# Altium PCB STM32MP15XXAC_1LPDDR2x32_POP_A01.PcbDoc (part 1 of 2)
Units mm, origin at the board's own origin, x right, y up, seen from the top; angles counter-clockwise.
Board outline 89 x 120 mm, 6 copper layers (Top Layer, Signal Layer 1, Signal Layer 2, Signal Layer 3, Signal Layer 4, Bottom Layer), stack 1.556 mm thick; 87 components, 99 nets, 895 pads, 462 vias.
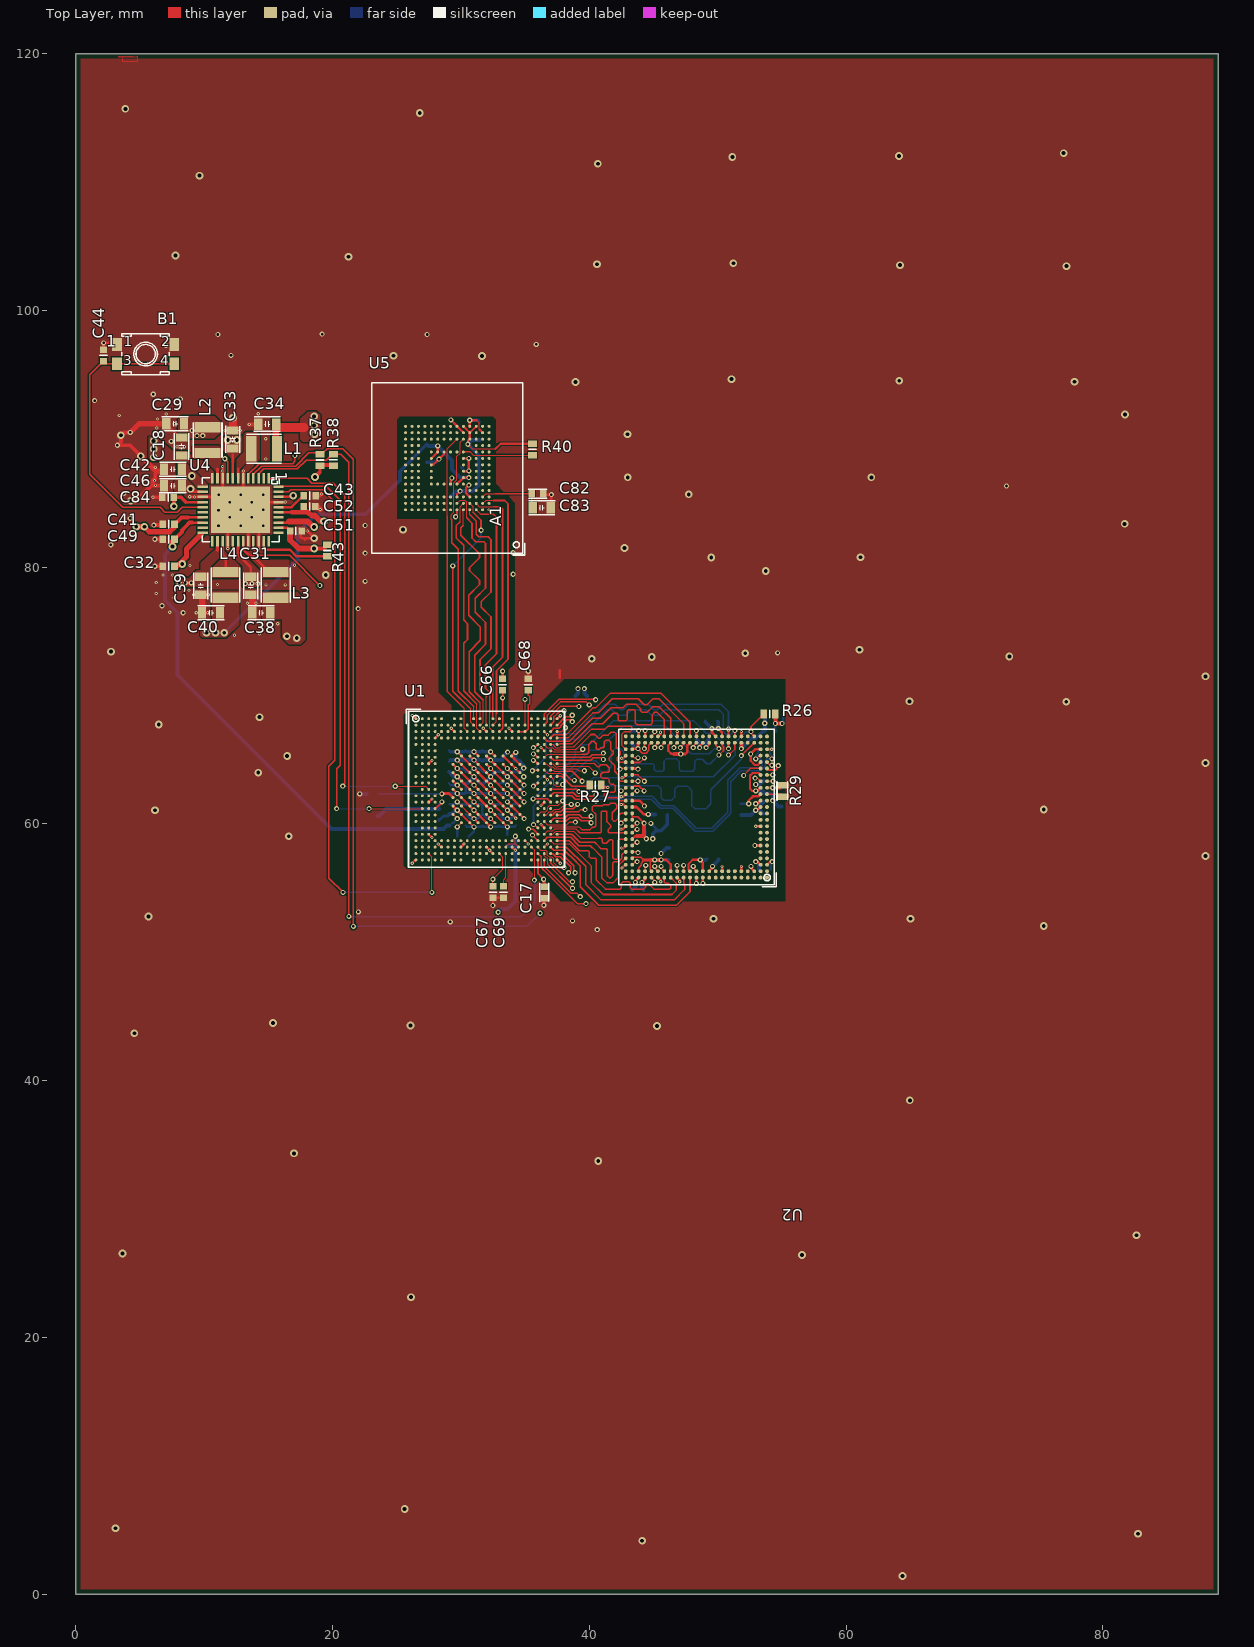
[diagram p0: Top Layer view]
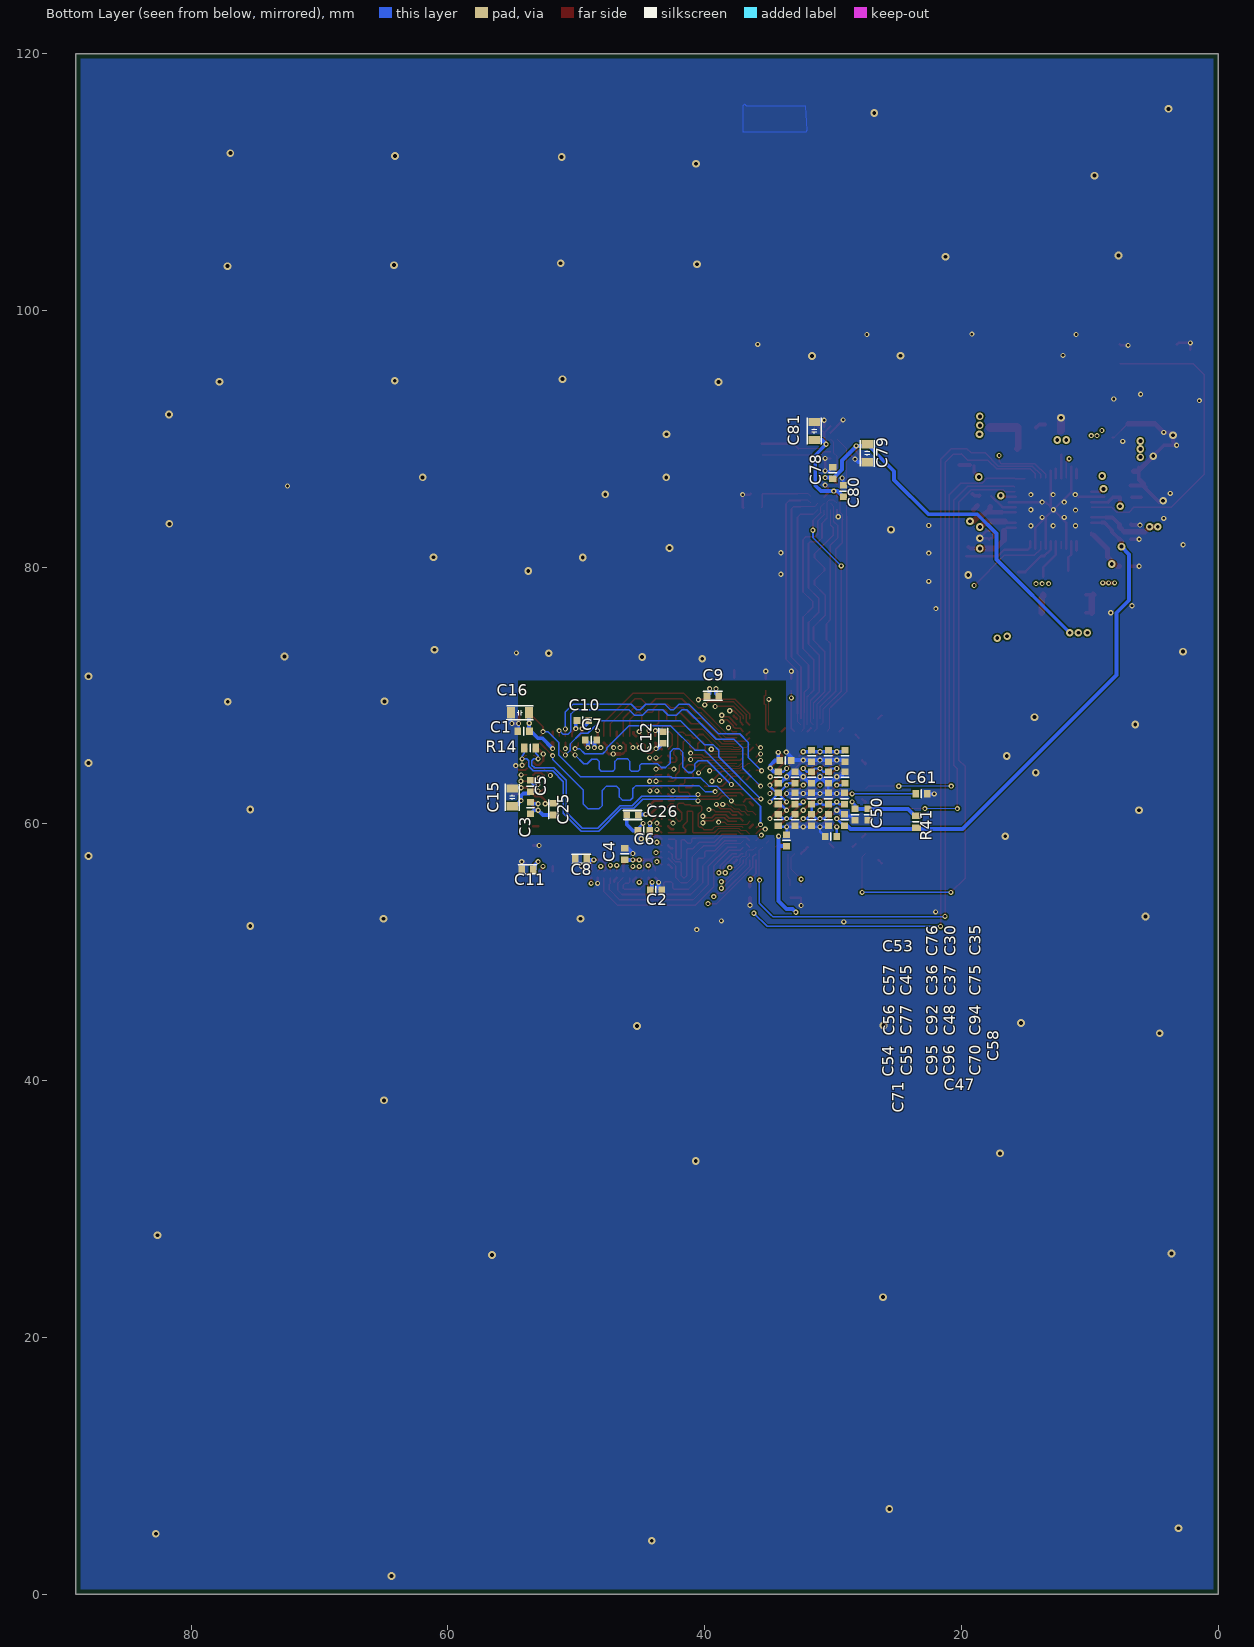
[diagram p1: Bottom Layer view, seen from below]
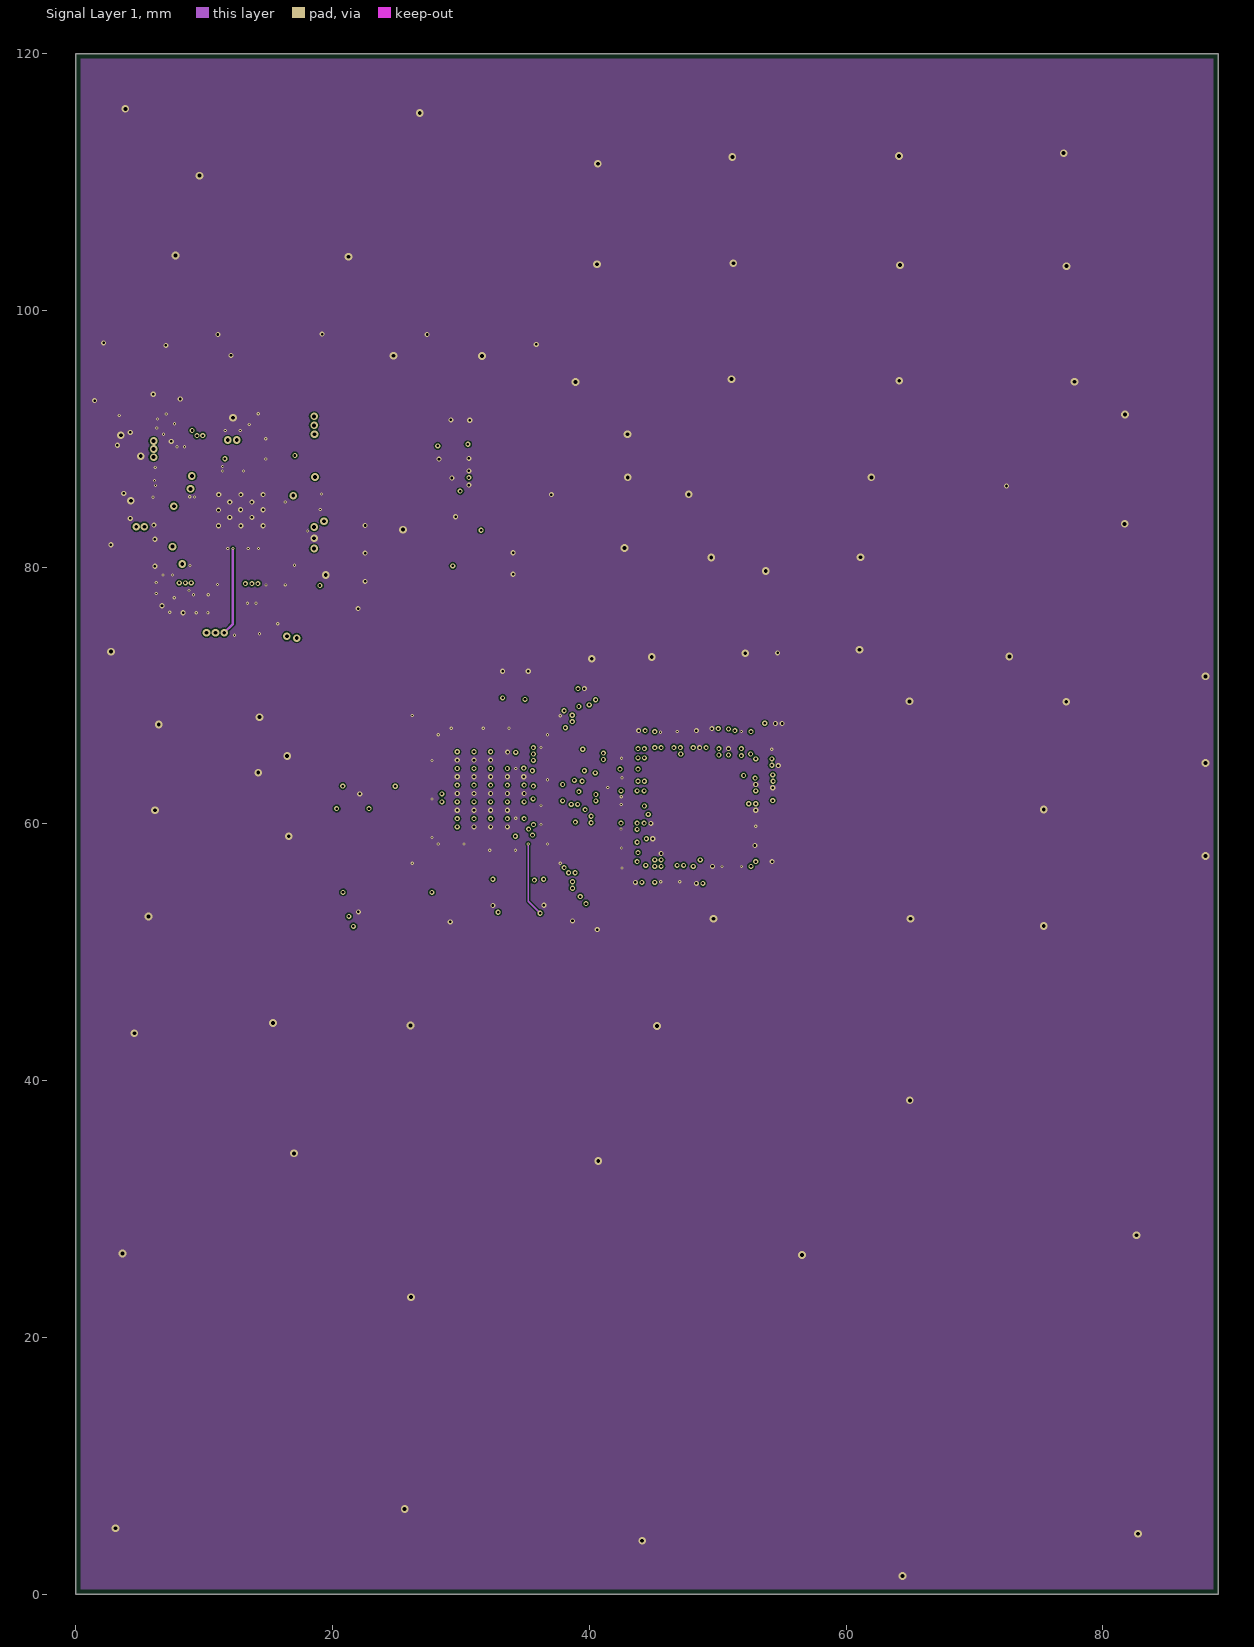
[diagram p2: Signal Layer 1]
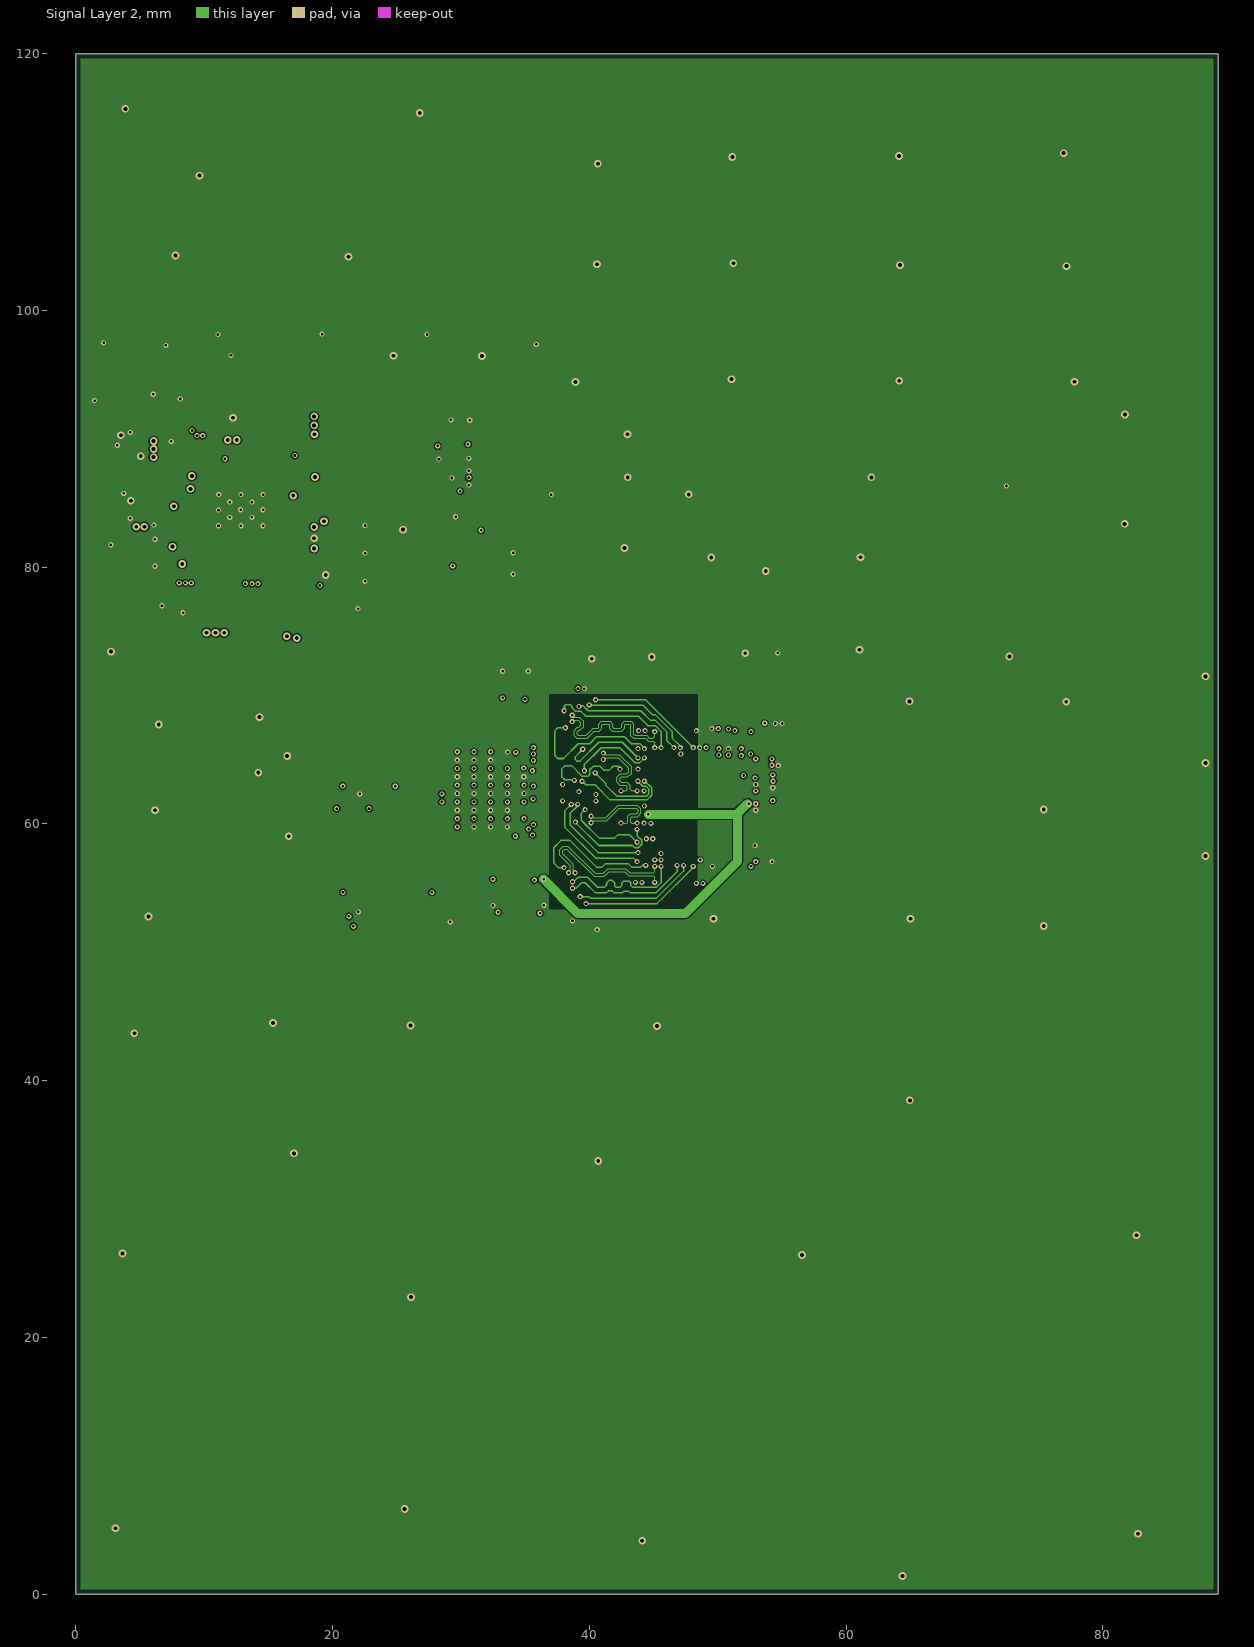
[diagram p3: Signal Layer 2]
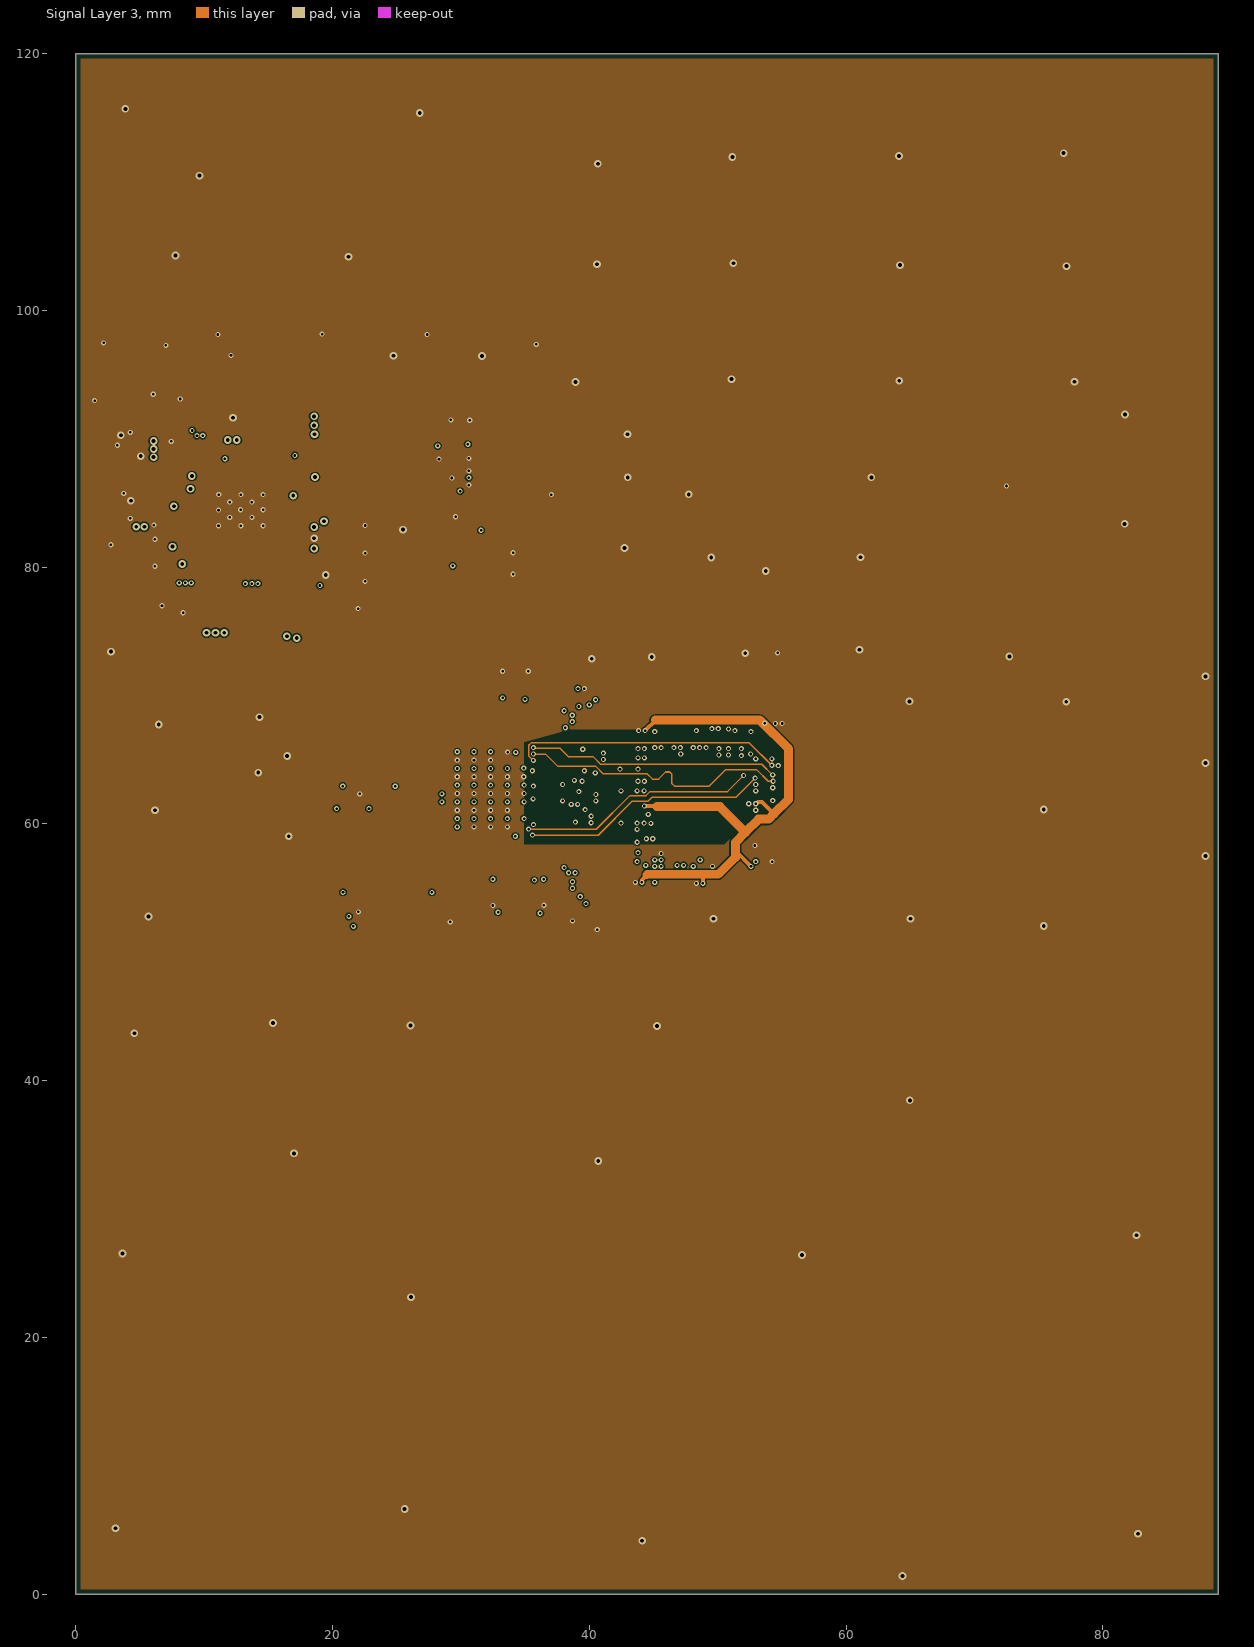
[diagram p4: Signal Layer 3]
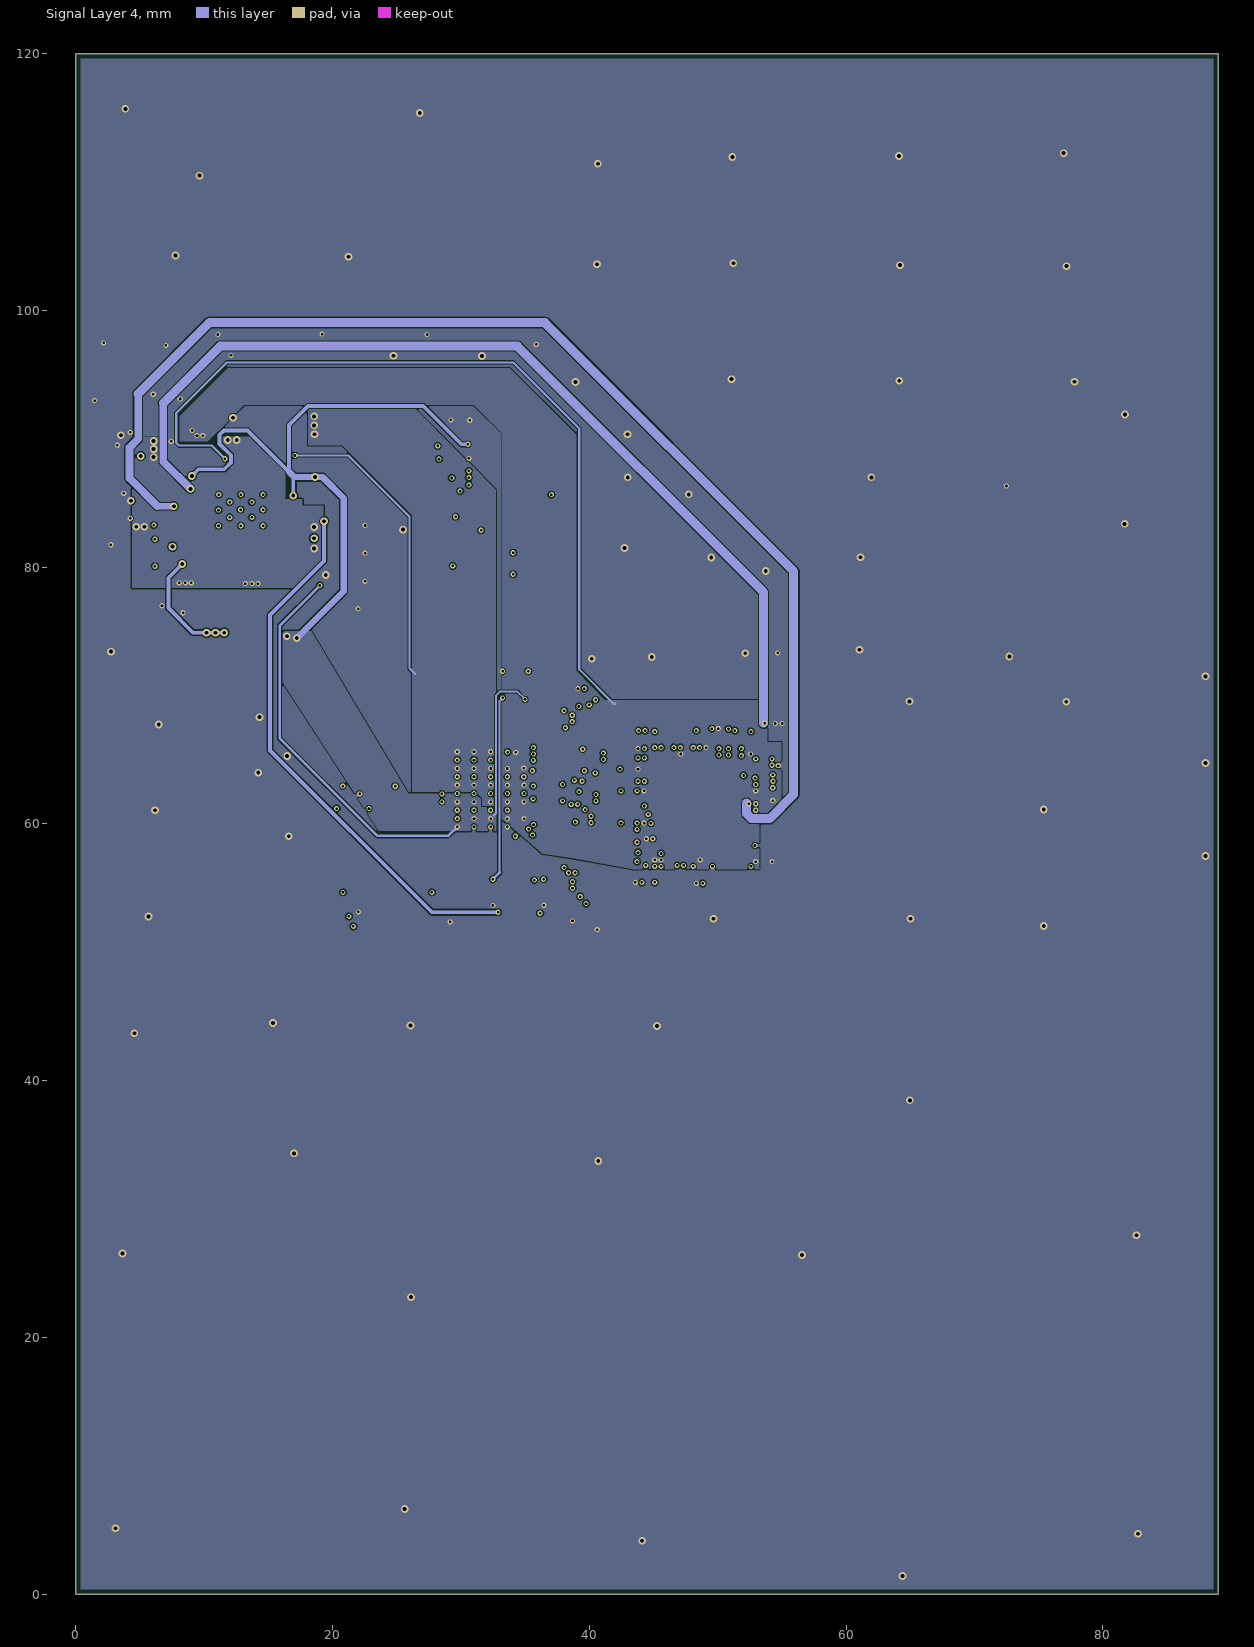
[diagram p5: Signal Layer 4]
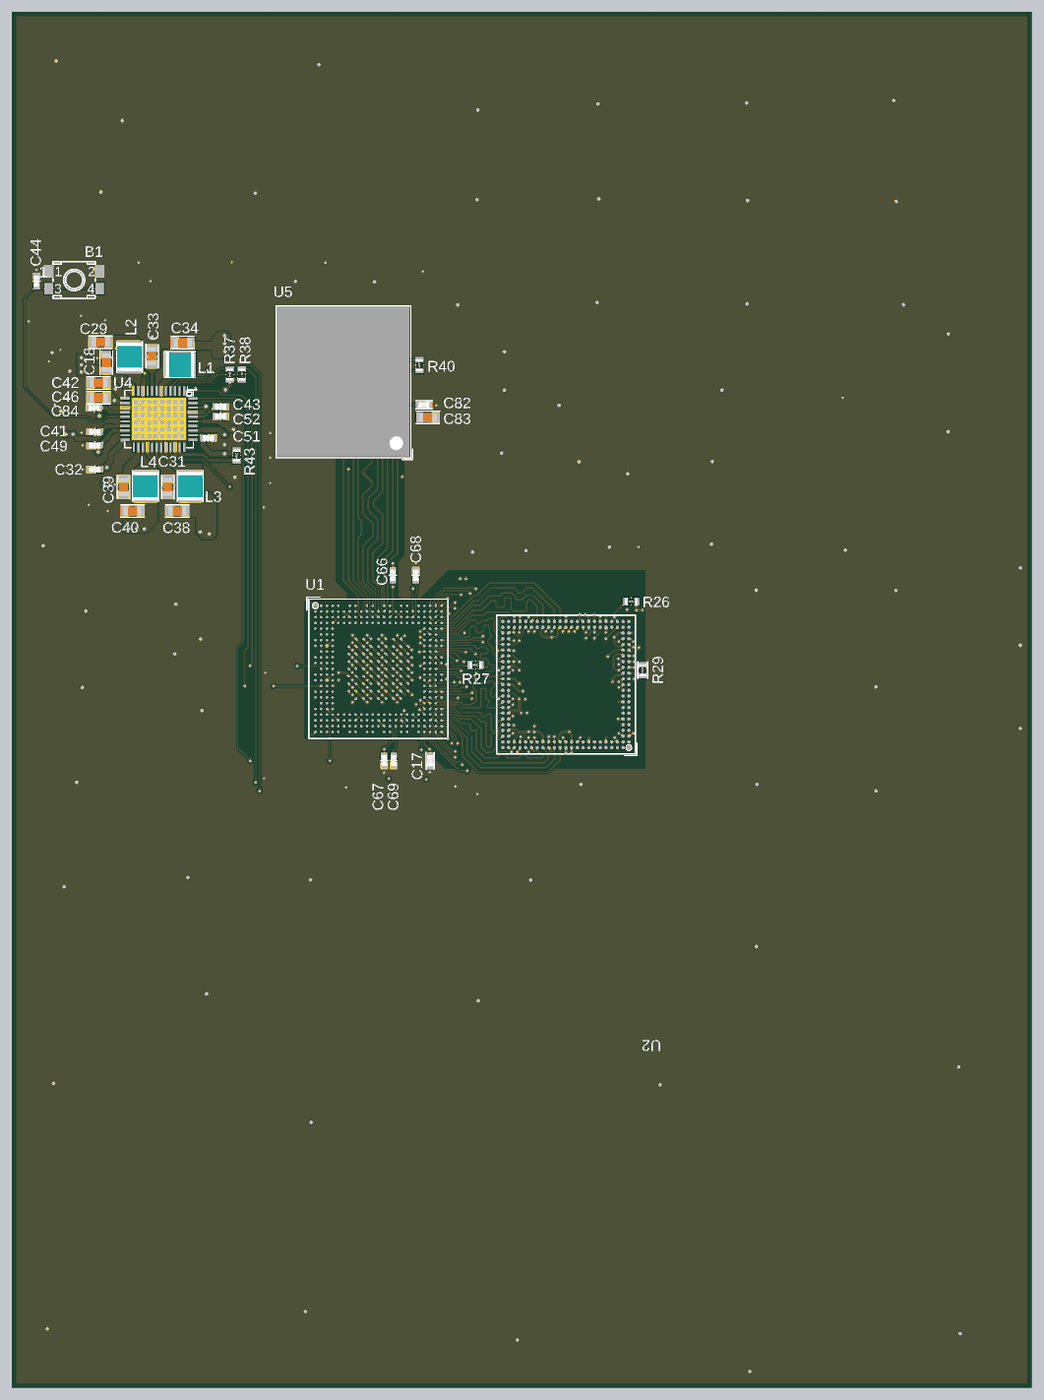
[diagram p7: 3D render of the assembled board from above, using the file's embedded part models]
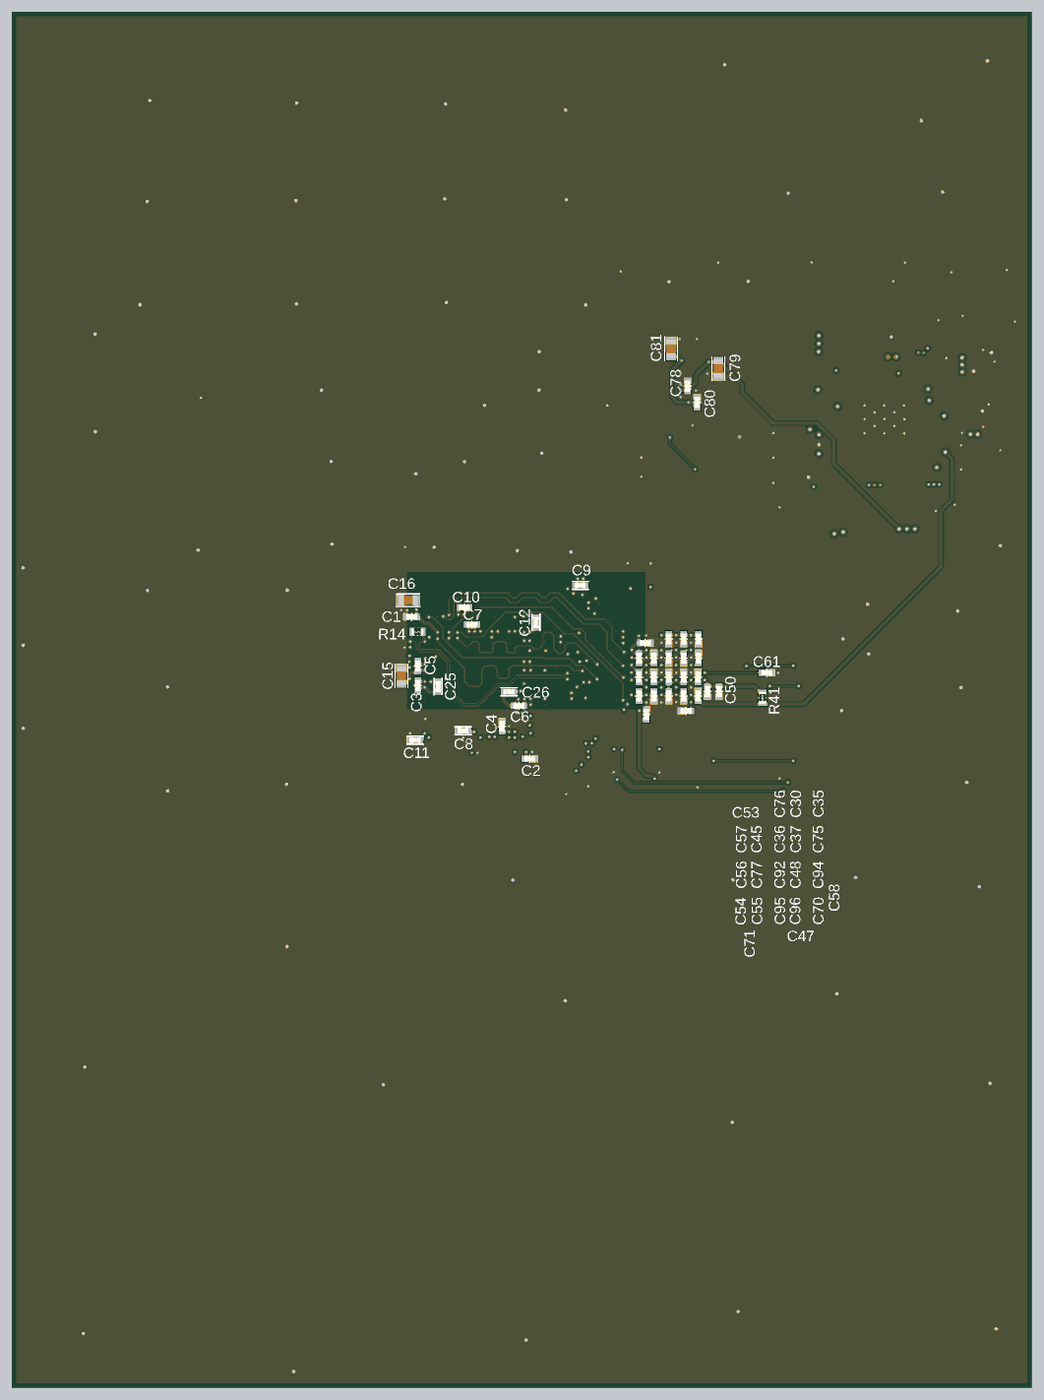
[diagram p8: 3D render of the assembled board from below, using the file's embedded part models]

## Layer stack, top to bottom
Top Solder: solder mask 0.0203, Solder Resist, Dk 3.5
Top Layer: signal copper 0.037
Dielectric 1: core 0.0986, FR-4, Dk 4.1
Signal Layer 1: signal copper 0.035
Dielectric 2: prepreg 0.13, Dk 4.25
Signal Layer 2: signal copper 0.035
Dielectric 3: core 0.885, Dk 4.25
Signal Layer 3: signal copper 0.035
Dielectric 4: prepreg 0.13, Dk 4.25
Signal Layer 4: signal copper 0.035
Dielectric 5: core 0.0986, Dk 4.1
Bottom Layer: signal copper 0.037
Bottom Solder: solder mask 0.0203, Solder Resist, Dk 3.5

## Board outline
89,120 89,0 0,0 0,120

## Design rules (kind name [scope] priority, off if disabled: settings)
BoardOutlineClearance [All] p1: gap=0.4 ignorepadtopadclearanceinfootprint=FALSE
Clearance diff [InNetClass('diff')] p1: gap=0.1 ignorepadtopadclearanceinfootprint=FALSE except(0: Arc-Hole Track-Hole SMDPad-Hole THPad-Hole Via-Hole Fill-Hole Poly-Hole Region-Hole Text-Hole; 0.08: Track-SMDPad; 0.13: Track-Track; 0.15: Arc-Fill Track-Fill SMDPad-Fill THPad-Fill Via-Fill Fill-Fill; 0.2: Arc-THPad SMDPad-SMDPad SMDPad-THPad THPad-THPad)
Clearance [InNetClass('All Nets')] p2: gap=0.1 ignorepadtopadclearanceinfootprint=FALSE except(0: Arc-Hole Track-Hole SMDPad-Hole THPad-Hole Via-Hole Fill-Hole Poly-Hole Region-Hole Text-Hole; 0.08: Track-Track Track-SMDPad; 0.15: Arc-Fill Track-Fill SMDPad-Fill THPad-Fill Via-Fill Fill-Fill)
ComponentClearance [All] p1 off: gap=0.025 collisioncheckmode=3 verticalgap=2540 showdistances=TRUE
DiffPairsRouting [All] p1: maxlimit=0.14 minlimit=0.13 mostfreqgap=0.14 toplayer_maxgap=0.13 toplayer_prefgap=0.13 toplayer_minwidth=0.09 toplayer_maxwidth=0.13 toplayer_prefwidth=0.1 midlayer1_maxgap=0.13 midlayer1_prefgap=0.13 midlayer1_minwidth=0.09 midlayer1_maxwidth=0.13 midlayer1_prefwidth=0.1 midlayer2_mingap=0.14 midlayer2_minwidth=0.09 midlayer2_maxwidth=0.09 midlayer2_prefwidth=0.09 midlayer3_prefgap=0.13 midlayer3_minwidth=0.09 midlayer3_maxwidth=0.13 midlayer3_prefwidth=0.1 midlayer4_maxgap=0.13 midlayer4_prefgap=0.13 midlayer4_minwidth=0.09 midlayer4_maxwidth=0.13 midlayer4_prefwidth=0.1 bottomlayer_maxgap=0.13 bottomlayer_prefgap=0.13 bottomlayer_minwidth=0.09 bottomlayer_maxwidth=0.13 bottomlayer_prefwidth=0.1 maxuncoupledlength=0.5
FanoutControl Fanout_BGA [IsBGA] p1: bgadir=Out bgaviamode=Closest fanoutstyle=Auto fanoutdirection=Alternating viagrid=0.025 // Fanout_BGA (Default Rule)
FanoutControl Fanout_LCC [IsLCC] p2: bgadir=Out bgaviamode=Closest fanoutstyle=Auto fanoutdirection=Alternating viagrid=0.025 // Fanout_LCC (Default Rule)
FanoutControl Fanout_SOIC [IsSOIC] p3: bgadir=Out bgaviamode=Closest fanoutstyle=Auto fanoutdirection=Alternating viagrid=0.025 // Fanout_SOIC (Default Rule)
FanoutControl Fanout_Small [(CompPinCount < 5)] p4: bgadir=Out bgaviamode=Closest fanoutstyle=Auto fanoutdirection=OutThenIn viagrid=0.025 // Fanout_Small (Default Rule)
FanoutControl Fanout_Default [All] p5: bgadir=Out bgaviamode=Closest fanoutstyle=Auto fanoutdirection=Alternating viagrid=0.025 // Fanout_Default (Default Rule)
Height [All] p1 off: minheight=0 maxheight=100 prefheight=0.5
HoleSize [All] p1: absolutevalues=TRUE maxlimit=10 minlimit=0.1 maxpercent=80.000 minpercent=20.000
HoleToHoleClearance [All] p1: gap=0.25 allowstackedmicrovias=TRUE
Length Length_SDMMC1 [InNetClass('NETC_SDMMC1')] p1: maxlimit=86 minlimit=81
MatchedLengths [All] p1: tolerance=25.4 checknetsindiffpair=FALSE checkdiffpairvsdiffpair=TRUE checkxsignals=TRUE checkothers=TRUE
MinimumSolderMaskSliver [All] p1: minsoldermaskwidth=0
PlaneClearance [All] p1: clearance=0.5
PlaneConnect [All] p1: planeconnectstyle=Direct reliefexpansion=0.508 reliefentries=4 reliefconductorwidth=0.254 reliefairgap=0.254
PolygonConnect PolygonConnect_notr [All vs (IsNamedPolygon('NO TR'))] p1: connectstyle=Direct reliefconductorwidth=0.254 reliefentries=4 polygonreliefangle="90 Angle" airgapwidth=0.254
PolygonConnect [All] p2: connectstyle=Direct reliefconductorwidth=0.254 reliefentries=4 polygonreliefangle="45 Angle" airgapwidth=0.254
RoomDefinition "U_1LPDDR2_32bits_POP " [InComponentClass('U_1LPDDR2_32bits_POP ')] p1: confinementstyle=ConfineIn formatcopy=TRUE lockcomponents=FALSE outline -876.725,-828.9 -825.925,-828.9 -825.925,-803.5 -876.725,-803.5
RoomDefinition U_STM32_MPU_IOs [InComponentClass('U_STM32_MPU_IOs')] p2 off: confinementstyle=ConfineIn formatcopy=TRUE lockcomponents=FALSE outline 88.575,2.075 139.375,2.075 139.375,27.475 88.575,27.475
RoomDefinition U_Power_MPU [InComponentClass('U_Power_MPU')] p3 off: confinementstyle=ConfineIn formatcopy=TRUE lockcomponents=FALSE outline 87.122,16.916 100.898,16.916 100.898,22.892 87.122,22.892
RoomDefinition U_eMMC [InComponentClass('U_eMMC')] p4 off: confinementstyle=ConfineIn formatcopy=TRUE lockcomponents=FALSE outline 87.122,1.416 129.449,1.416 129.449,15.666 87.122,15.666
RoomDefinition U_Power_PMIC [InComponentClass('U_Power_PMIC')] p5 off: confinementstyle=ConfineIn formatcopy=TRUE lockcomponents=FALSE outline 87.122,8.666 203.578,8.666 203.578,17.666 87.122,17.666
RoutingVias RoutingVias_GND [InNetClass('GND')] p1: holewidth=0.3 width=0.6 viastyle="Through Hole" minholewidth=0.1 minwidth=0.25 maxholewidth=0.3 maxwidth=0.6
RoutingVias RoutingVias_ALIMS [InNetClass('ALIMS')] p2: holewidth=0.3 width=0.6 viastyle="Through Hole" minholewidth=0.2 minwidth=0.4 maxholewidth=0.3 maxwidth=0.6
RoutingVias [All] p3: holewidth=0.2 width=0.4 viastyle="Through Hole" minholewidth=0.1 minwidth=0.25 maxholewidth=0.3 maxwidth=0.6
SilkToSilkClearance [All] p1: silktosilkclearance=0
SilkToSolderMaskClearance [IsPad] p1: minsilkscreentomaskgap=0 clearancetoexposedcopper=TRUE
SolderMaskExpansion [All] p1: expansion=0.05 istentingtop=FALSE
Width Width_VDD1 [InNet('VDD1_DDR')] p1: maxlimit=0.7 minlimit=0.2 preferedwidth=0.3
Width Width_1 [InNet('VREF_DDR')] p2: maxlimit=0.7 minlimit=0.15 preferedwidth=0.2
Width VDD2_DDR [InNet('VDD2_DDR')] p3: maxlimit=0.5 minlimit=0.1 preferedwidth=0.175
Width Width_VCORE [InNet('VDD_CORE')] p4: maxlimit=0.7 minlimit=0.1 preferedwidth=0.3 midlayer1_minwidth=0.12 midlayer2_minwidth=0.12 midlayer3_minwidth=0.12 midlayer4_minwidth=0.12 bottomlayer_minwidth=0.12 minimp=50.000000 maximp=50.000000 favimp=50.000000
Width Width_gnd [InNet('GND')] p5: maxlimit=0.7 minlimit=0.09 preferedwidth=0.2
Width [All] p6: maxlimit=0.6 minlimit=0.09 preferedwidth=0.12 midlayer1_minwidth=0.1 midlayer1_prefwidth=0.1 midlayer2_minwidth=0.12 midlayer3_minwidth=0.12 midlayer4_minwidth=0.1 midlayer4_prefwidth=0.1 minimp=50.000000 maximp=50.000000 favimp=50.000000
15 further rules are at their usual default settings.

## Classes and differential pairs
differential pair class DIFF_CLK: DDR_CLK
differential pair class DIFF_DQS1: DDR_DQS1
differential pair class DIFF_DQS0: DDR_DQS0
polygon class POLY_DIRECT_ALL: NETC906_2_L01_P192
component class U_Power_MPU: C30 C35 C36 C37 C45 C47 C48 C50 C53 C54 C55 C56 C57 C58 C61 C66 C67 C68 C69 C70 C71 C75 C76 C77 C92 C94 C95 C96 R41
component class U_Power_PMIC: B1 C18 C29 C31 C32 C33 C34 C38 C39 C40 C41 C42 C43 C44 C46 C49 C51 C52 C84 L1 L2 L3 L4 R43 U4
component class U_eMMC: C78 C79 C80 C81 C82 C83 R40 U5
component class U_STM32_MPU_IOs: C17 R27 R37 R38 U1
net class eMMC_SDIO2_D[0..7]: eMMC_SDIO2_D0 eMMC_SDIO2_D1 eMMC_SDIO2_D2 eMMC_SDIO2_D3 eMMC_SDIO2_D4 eMMC_SDIO2_D5 eMMC_SDIO2_D6 eMMC_SDIO2_D7
component class "U_1LPDDR2_32bits_POP ": C1 C2 C3 C4 C5 C6 C7 C8 C9 C10 C11 C12 C15 C16 C25 C26 R14 R26 R29 U2
differential pair DDR_CLK: +DDR_CLK_P -DDR_CLK_N
differential pair DDR_DQS0: +DDR_DQS0_P -DDR_DQS0_N
differential pair DDR_DQS1: +DDR_DQS1_P -DDR_DQS1_N
differential pair DDR_DQS2: +DDR_DQS2_P -DDR_DQS2_N
differential pair DDR_DQS3: +DDR_DQS3_P -DDR_DQS3_N

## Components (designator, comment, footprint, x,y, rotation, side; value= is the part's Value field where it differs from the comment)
B1 "SW-PUSH-TS-02H-Blue" SWI_JIUBABA_C-TS-02H-2-5-B-V-T_R_BLUE 5.45,96.6 r0 top
C1 "Capacitor" C0402 54.1,67.225 r0 bottom value=100nF
C2 "Capacitor" C0402 43.8,54.85 r180 bottom value=100nF
C3 "Capacitor" C0402 53.575,61.25 r270 bottom value=100nF
C4 "Capacitor" C0402 46.225,57.675 r90 bottom value=100nF
C5 "Capacitor" C0402 53.575,62.95 r90 bottom value=100nF
C6 "Capacitor" C0402 44.75,59.475 r0 bottom value=100nF
C7 "Capacitor" C0402 48.85,66.55 r180 bottom value=100nF
C8 "Capacitor" C0402 49.625,57.3 r0 bottom value=100nF
C9 "Capacitor" C0402 39.375,69.975 r0 bottom value=100nF
C10 "Capacitor" C0402 49.5,68.05 r180 bottom value=100nF
C11 "Capacitor" C0402 53.8,56.475 r0 bottom value=100nF
C12 "Capacitor" C0402 43.25,66.75 r90 bottom value=100nF
C15 "Capacitor" C0603 55,62.075 r270 bottom value=10uF
C16 "Capacitor" C0603 54.4,68.675 r180 bottom value=10uF
C17 "Capacitor" C0402 36.5,54.675 r270 top value=100nF
C18 "Capacitor" C0603 8.25,89.4 r270 top value=10uF
C25 "Capacitor" C0402 51.8,61.15 r270 bottom value=100nF
C26 "Capacitor" C0402 45.625,60.7 r0 bottom value=100nF
C29 "Capacitor" C0603 7.75,91.175 r0 top value=22uF
C30 "Capacitor" C0402 30.375,65.3 r90 bottom value=1uF
C31 "Capacitor" C0603 13.625,78.55 r90 top value=10uF
C32 "Capacitor" C0402 7.25,80.075 r0 top value=1uF
C33 "Capacitor" C0603 12.25,89.95 r270 top value=10uF
C34 "Capacitor" C0603 14.925,91.15 r0 top value=22uF
C35 "Capacitor" C0402 29.075,65.3 r90 bottom value=1uF
C36 "Capacitor" C0402 31.675,63.625 r90 bottom value=1uF
C37 "Capacitor" C0402 30.375,63.625 r90 bottom value=1uF
C38 "Capacitor" C0603 14.45,76.45 r0 top value=22uF
C39 "Capacitor" C0603 9.75,78.55 r90 top value=10uF
C40 "Capacitor" C0603 10.55,76.45 r0 top value=22uF
C41 "Capacitor" C0402 7.25,83.35 r0 top value=1uF
C42 "Capacitor" C0603 7.575,87.625 r0 top value=10uF
C43 "Capacitor" C0402 18.234,85.562 r0 top value=4.7uF
C44 "Capacitor" C0402 2.175,96.5 r270 top value=10nF
C45 "Capacitor" C0402 32.975,63.625 r270 bottom value=1uF
C46 "Capacitor" C0603 7.575,86.35 r0 top value=10uF
C47 "Capacitor" C0402 30.175,59.025 r180 bottom value=1uF
C48 "Capacitor" C0402 30.375,61.975 r270 bottom value=1uF
C49 "Capacitor" C0402 7.25,82.175 r0 top value=4.7uF
C50 "Capacitor" C0402 27.275,60.725 r90 bottom value=1uF
C51 "Capacitor" C0402 17.15,82.825 r180 top value=4.7uF
C52 "Capacitor" C0402 18.225,84.725 r180 top value=4.7uF
C53 "Capacitor" C0402 33.725,64.95 r0 bottom value=1uF
C54 "Capacitor" C0402 34.275,60.325 r90 bottom value=1uF
C55 "Capacitor" C0402 32.975,60.325 r90 bottom value=1uF
C56 "Capacitor" C0402 34.275,61.975 r90 bottom value=820pF
C57 "Capacitor" C0402 34.275,63.625 r90 bottom value=820pF
C58 "Capacitor" C0402 28.3,60.725 r90 bottom value=10nF
C61 "Capacitor" C0402 23.125,62.35 r0 bottom value=100nF
C66 "Capacitor" C0402 33.25,70.85 r270 top value=100nF
C67 "Capacitor" C0402 32.5,54.7 r90 top value=2.2uF
C68 "Capacitor" C0402 35.25,70.85 r270 top value=2.2uF
C69 "Capacitor" C0402 33.325,54.7 r90 top value=2.2uF
C70 "Capacitor" C0402 29.125,60.325 r270 bottom value=1uF
C71 "Capacitor" C0402 33.625,58.725 r270 bottom value=100nF
C75 "Capacitor" C0402 29.075,63.625 r270 bottom value=1uF
C76 "Capacitor" C0402 31.675,65.3 r90 bottom value=1uF
C77 "Capacitor" C0402 32.975,61.975 r270 bottom value=1uF
C78 "Capacitor" C0402 30.025,87.35 r270 bottom value=100nF
C79 "Capacitor" C0603 27.35,88.875 r90 bottom value=2.2uF
C80 "Capacitor" C0402 29.2,85.925 r270 bottom value=100nF
C81 "Capacitor" C0603 31.475,90.6 r270 bottom value=2.2uF
C82 "Capacitor" C0402 35.975,85.725 r180 top value=100nF
C83 "Capacitor" C0603 36.3,84.625 r180 top value=2.2uF
C84 "Capacitor" C0402 7.2,85.45 r0 top value=1uF
C92 "Capacitor" C0402 31.675,61.975 r270 bottom value=1uF
C94 "Capacitor" C0402 29.125,61.975 r270 bottom value=1uF
C95 "Capacitor" C0402 31.675,60.325 r90 bottom value=1uF
C96 "Capacitor" C0402 30.375,60.325 r90 bottom value=1uF
L1 "IND_1uH_42mohm_3.2A" IND_2520_TOKO_DFE252012P 14.675,89.225 r0 top value=1uH
L2 "IND_1uH_42mohm_3.2A" IND_2520_TOKO_DFE252012P 10.275,89.9 r90 top value=1uH
L3 "IND_1uH_42mohm_3.2A" IND_2520_TOKO_DFE252012P 15.575,78.625 r270 top value=1uH
L4 "IND_1uH_42mohm_3.2A" IND_2520_TOKO_DFE252012P 11.675,78.625 r270 top value=1uH
R14 "Resistor" R0402 53.6,65.925 r0 bottom value=100R
R26 "Resistor" R0402 54.05,68.575 r180 top value=10K
R27 "Resistor" R0402 40.475,63.025 r0 top value="240R 1%"
R29 "Resistor" R0402 55.05,62.575 r270 top value=240R
R37 "Resistor" R0402 19.025,88.35 r90 top value=1K5
R38 "Resistor" R0402 20.074,88.363 r90 top value=1K5
R40 "Resistor" R0402 35.575,89.175 r90 top value=10K
R41 "Resistor" R0402 23.5,60.175 r90 bottom value=0R
R43 "Resistor" R0402 19.625,81.3 r90 top value=47K
U1 "STM32MP157CAC3" ICC_TFBGA361_12X12_STM32MP157CAC3_P050-065 32,62.7 r0 top locked
U2 "IS43LD32128A-18BPL" ICC_FBGA168_12X12_EDB4432BBPA_P050 48.35,61.325 r180 top locked
U4 "STPMU1" ICC_WFQFN44-EPAD_5X6_P040 12.85,84.475 r270 top value=STPMU1A
U5 "eMMC_THGBMDG5D1LBAIL" ICC_P-WFBGA153_13X11P5_P050 28.95,87.725 r90 top locked value=THGBMDG5D1LBAIL

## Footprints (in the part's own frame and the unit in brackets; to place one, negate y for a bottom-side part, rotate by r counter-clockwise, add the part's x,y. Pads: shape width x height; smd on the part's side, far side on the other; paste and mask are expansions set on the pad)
C0402 [mm]
  rect 0.51x0.56 smd mask+0.05: 1(-0.45,0) 2(0.45,0)
  silkscreen extent 0,-0.3 0,0.3, body extent -0.5,-0.3 0.5,0.3, height 0.4
C0603 [mm]
  rect 0.64x0.89 smd mask+0.05: 1(-0.7,0) 2(0.7,0)
  silkscreen extent -1.05,-0.55 1.02,0.55, body extent -0.9,-0.5 0.9,0.5, height 1.4
ICC_FBGA168_12X12_EDB4432BBPA_P050 [mm]
  round 0.3 smd mask+0.05: A1(-5.5,5.5) A2(-5,5.5) A3(-4.5,5.5) A4(-4,5.5) A5(-3.5,5.5) A6(-3,5.5) A7(-2.5,5.5) A8(-2,5.5) A9(-1.5,5.5) A10(-1,5.5) A11(-0.5,5.5) A12(0,5.5) A13(0.5,5.5) A14(1,5.5) A15(1.5,5.5) A16(2,5.5) A17(2.5,5.5) A18(3,5.5) A19(3.5,5.5) A20(4,5.5) A21(4.5,5.5) A22(5,5.5) A23(5.5,5.5) AA1(-5.5,-4.5) AA2(-5,-4.5) AA22(5,-4.5) AA23(5.5,-4.5) AB1(-5.5,-5) AB2(-5,-5) AB3(-4.5,-5) AB4(-4,-5) AB5(-3.5,-5) AB6(-3,-5) AB7(-2.5,-5) AB8(-2,-5) AB9(-1.5,-5) AB10(-1,-5) AB11(-0.5,-5) AB12(0,-5) AB13(0.5,-5) AB14(1,-5) AB15(1.5,-5) AB16(2,-5) AB17(2.5,-5) AB18(3,-5) AB19(3.5,-5) AB20(4,-5) AB21(4.5,-5) AB22(5,-5) AB23(5.5,-5) AC1(-5.5,-5.5) AC2(-5,-5.5) AC3(-4.5,-5.5) AC4(-4,-5.5) AC5(-3.5,-5.5) AC6(-3,-5.5) AC7(-2.5,-5.5) AC8(-2,-5.5) AC9(-1.5,-5.5) AC10(-1,-5.5) AC11(-0.5,-5.5) AC12(0,-5.5) AC13(0.5,-5.5) AC14(1,-5.5) AC15(1.5,-5.5) AC16(2,-5.5) AC17(2.5,-5.5) AC18(3,-5.5) AC19(3.5,-5.5) AC20(4,-5.5) AC21(4.5,-5.5) AC22(5,-5.5) AC23(5.5,-5.5) B1(-5.5,5) B2(-5,5) B3(-4.5,5) B4(-4,5) B5(-3.5,5) B6(-3,5) B7(-2.5,5) B8(-2,5) B9(-1.5,5) B10(-1,5) B11(-0.5,5) B12(0,5) B13(0.5,5) B14(1,5) B15(1.5,5) B16(2,5) B17(2.5,5) B18(3,5) B19(3.5,5) B20(4,5) B21(4.5,5) B22(5,5) B23(5.5,5) C1(-5.5,4.5) C2(-5,4.5) C22(5,4.5) C23(5.5,4.5) D1(-5.5,4) D2(-5,4) D22(5,4) D23(5.5,4) E1(-5.5,3.5) E2(-5,3.5) E22(5,3.5) E23(5.5,3.5) F1(-5.5,3) F2(-5,3) F22(5,3) F23(5.5,3) G1(-5.5,2.5) G2(-5,2.5) G22(5,2.5) G23(5.5,2.5) H1(-5.5,2) H2(-5,2) H22(5,2) H23(5.5,2) J1(-5.5,1.5) J2(-5,1.5) J22(5,1.5) J23(5.5,1.5) K1(-5.5,1) K2(-5,1) K22(5,1) K23(5.5,1) L1(-5.5,0.5) L2(-5,0.5) L22(5,0.5) L23(5.5,0.5) M1(-5.5,0) M2(-5,0) M22(5,0) M23(5.5,0) N1(-5.5,-0.5) N2(-5,-0.5) N22(5,-0.5) N23(5.5,-0.5) P1(-5.5,-1) P2(-5,-1) P22(5,-1) P23(5.5,-1) R1(-5.5,-1.5) R2(-5,-1.5) R22(5,-1.5) R23(5.5,-1.5) T1(-5.5,-2) T2(-5,-2) T22(5,-2) T23(5.5,-2) U1(-5.5,-2.5) U2(-5,-2.5) U22(5,-2.5) U23(5.5,-2.5) V1(-5.5,-3) V2(-5,-3) V22(5,-3) V23(5.5,-3) W1(-5.5,-3.5) W2(-5,-3.5) W22(5,-3.5) W23(5.5,-3.5) Y1(-5.5,-4) Y2(-5,-4) Y22(5,-4) Y23(5.5,-4)
  silkscreen extent -6.2,-6.05 6.05,6.2, body extent -6.35,-7.55 6.05,6.56, height 1.2
ICC_P-WFBGA153_13X11P5_P050 [mm]
  round 0.23 smd mask+0.05: A1(-3.25,-3.25) A2(-3.25,-2.75) A3(-3.25,-2.25) A4(-3.25,-1.75) A5(-3.25,-1.25) A6(-3.25,-0.75) A7(-3.25,-0.25) A8(-3.25,0.25) A9(-3.25,0.75) A10(-3.25,1.25) A11(-3.25,1.75) A12(-3.25,2.25) A13(-3.25,2.75) A14(-3.25,3.25) B1(-2.75,-3.25) B2(-2.75,-2.75) B3(-2.75,-2.25) B4(-2.75,-1.75) B5(-2.75,-1.25) B6(-2.75,-0.75) B7(-2.75,-0.25) B8(-2.75,0.25) B9(-2.75,0.75) B10(-2.75,1.25) B11(-2.75,1.75) B12(-2.75,2.25) B13(-2.75,2.75) B14(-2.75,3.25) C1(-2.25,-3.25) C2(-2.25,-2.75) C3(-2.25,-2.25) C4(-2.25,-1.75) C5(-2.25,-1.25) C6(-2.25,-0.75) C7(-2.25,-0.25) C8(-2.25,0.25) C9(-2.25,0.75) C10(-2.25,1.25) C11(-2.25,1.75) C12(-2.25,2.25) C13(-2.25,2.75) C14(-2.25,3.25) D1(-1.75,-3.25) D2(-1.75,-2.75) D3(-1.75,-2.25) D4(-1.75,-1.75) D12(-1.75,2.25) D13(-1.75,2.75) D14(-1.75,3.25) E1(-1.25,-3.25) E2(-1.25,-2.75) E3(-1.25,-2.25) E5(-1.25,-1.25) E6(-1.25,-0.75) E7(-1.25,-0.25) E8(-1.25,0.25) E9(-1.25,0.75) E10(-1.25,1.25) E12(-1.25,2.25) E13(-1.25,2.75) E14(-1.25,3.25) F1(-0.75,-3.25) F2(-0.75,-2.75) F3(-0.75,-2.25) F5(-0.75,-1.25) F10(-0.75,1.25) F12(-0.75,2.25) F13(-0.75,2.75) F14(-0.75,3.25) G1(-0.25,-3.25) G2(-0.25,-2.75) G3(-0.25,-2.25) G5(-0.25,-1.25) G10(-0.25,1.25) G12(-0.25,2.25) G13(-0.25,2.75) G14(-0.25,3.25) H1(0.25,-3.25) H2(0.25,-2.75) H3(0.25,-2.25) H5(0.25,-1.25) H10(0.25,1.25) H12(0.25,2.25) H13(0.25,2.75) H14(0.25,3.25) J1(0.75,-3.25) J2(0.75,-2.75) J3(0.75,-2.25) J5(0.75,-1.25) J10(0.75,1.25) J12(0.75,2.25) J13(0.75,2.75) J14(0.75,3.25) K1(1.25,-3.25) K2(1.25,-2.75) K3(1.25,-2.25) K5(1.25,-1.25) K6(1.25,-0.75) K7(1.25,-0.25) K8(1.25,0.25) K9(1.25,0.75) K10(1.25,1.25) K12(1.25,2.25) K13(1.25,2.75) K14(1.25,3.25) L1(1.75,-3.25) L2(1.75,-2.75) L3(1.75,-2.25) L12(1.75,2.25) L13(1.75,2.75) L14(1.75,3.25) M1(2.25,-3.25) M2(2.25,-2.75) M3(2.25,-2.25) M4(2.25,-1.75) M5(2.25,-1.25) M6(2.25,-0.75) M7(2.25,-0.25) M8(2.25,0.25) M9(2.25,0.75) M10(2.25,1.25) M11(2.25,1.75) M12(2.25,2.25) M13(2.25,2.75) M14(2.25,3.25) N1(2.75,-3.25) N2(2.75,-2.75) N3(2.75,-2.25) N4(2.75,-1.75) N5(2.75,-1.25) N6(2.75,-0.75) N7(2.75,-0.25) N8(2.75,0.25) N9(2.75,0.75) N10(2.75,1.25) N11(2.75,1.75) N12(2.75,2.25) N13(2.75,2.75) N14(2.75,3.25) P1(3.25,-3.25) P2(3.25,-2.75) P3(3.25,-2.25) P4(3.25,-1.75) P5(3.25,-1.25) P6(3.25,-0.75) P7(3.25,-0.25) P8(3.25,0.25) P9(3.25,0.75) P10(3.25,1.25) P11(3.25,1.75) P12(3.25,2.25) P13(3.25,2.75) P14(3.25,3.25)
  silkscreen extent -6.78,-6.02 6.63,5.87, body extent -6.55,-5.8 6.55,5.8, height 1
ICC_TFBGA361_12X12_STM32MP157CAC3_P050-065 [mm] "IPC"
  round 0.23 smd mask+0.05: 1A2(-1.95,2.6) 1A3(-1.3,2.6) 1A4(-0.65,2.6) 1A5(0,2.6) 1A6(0.65,2.6) 1A7(1.3,2.6) 1A8(1.95,2.6) 1B1(-2.6,1.95) 1B2(-1.95,1.95) 1B3(-1.3,1.95) 1B4(-0.65,1.95) 1B5(0,1.95) 1B6(0.65,1.95) 1B7(1.3,1.95) 1B8(1.95,1.95) 1B9(2.6,1.95) 1C1(-2.6,1.3) 1C2(-1.95,1.3) 1C3(-1.3,1.3) 1C4(-0.65,1.3) 1C5(0,1.3) 1C6(0.65,1.3) 1C7(1.3,1.3) 1C8(1.95,1.3) 1C9(2.6,1.3) 1D1(-2.6,0.65) 1D2(-1.95,0.65) 1D3(-1.3,0.65) 1D4(-0.65,0.65) 1D5(0,0.65) 1D6(0.65,0.65) 1D7(1.3,0.65) 1D8(1.95,0.65) 1D9(2.6,0.65) 1E1(-2.6,0) 1E2(-1.95,0) 1E3(-1.3,0) 1E4(-0.65,0) 1E5(0,0) 1E6(0.65,0) 1E7(1.3,0) 1E8(1.95,0) 1E9(2.6,0) 1F1(-2.6,-0.65) 1F2(-1.95,-0.65) 1F3(-1.3,-0.65) 1F4(-0.65,-0.65) 1F5(0,-0.65) 1F6(0.65,-0.65) 1F7(1.3,-0.65) 1F8(1.95,-0.65) 1F9(2.6,-0.65) 1G1(-2.6,-1.3) 1G2(-1.95,-1.3) 1G3(-1.3,-1.3) 1G4(-0.65,-1.3) 1G5(0,-1.3) 1G6(0.65,-1.3) 1G7(1.3,-1.3) 1G8(1.95,-1.3) 1G9(2.6,-1.3) 1H1(-2.6,-1.95) 1H2(-1.95,-1.95) 1H3(-1.3,-1.95) 1H4(-0.65,-1.95) 1H5(0,-1.95) 1H6(0.65,-1.95) 1H7(1.3,-1.95) 1H8(1.95,-1.95) 1H9(2.6,-1.95) 1J2(-1.95,-2.6) 1J3(-1.3,-2.6) 1J4(-0.65,-2.6) 1J5(0,-2.6) 1J6(0.65,-2.6) 1J7(1.3,-2.6) 1J8(1.95,-2.6) A1(-5.5,5.5) A2(-5,5.5) A3(-4.5,5.5) A4(-4,5.5) A5(-3.5,5.5) A7(-2.5,5.5) A8(-2,5.5) A10(-1,5.5) A11(-0.5,5.5) A13(0.5,5.5) A14(1,5.5) A16(2,5.5) A17(2.5,5.5) A19(3.5,5.5) A20(4,5.5) A21(4.5,5.5) A22(5,5.5) A23(5.5,5.5) AA1(-5.5,-4.5) AA2(-5,-4.5) AA3(-4.5,-4.5) AA4(-4,-4.5) AA5(-3.5,-4.5) AA6(-3,-4.5) AA7(-2.5,-4.5) AA8(-2,-4.5) AA9(-1.5,-4.5) AA10(-1,-4.5) AA11(-0.5,-4.5) AA12(0,-4.5) AA13(0.5,-4.5) AA14(1,-4.5) AA15(1.5,-4.5) AA16(2,-4.5) AA17(2.5,-4.5) AA18(3,-4.5) AA19(3.5,-4.5) AA20(4,-4.5) AA21(4.5,-4.5) AA22(5,-4.5) AA23(5.5,-4.5) AB1(-5.5,-5) AB2(-5,-5) AB3(-4.5,-5) AB4(-4,-5) AB5(-3.5,-5) AB6(-3,-5) AB7(-2.5,-5) AB8(-2,-5) AB9(-1.5,-5) AB10(-1,-5) AB11(-0.5,-5) AB12(0,-5) AB13(0.5,-5) AB14(1,-5) AB15(1.5,-5) AB16(2,-5) AB17(2.5,-5) AB18(3,-5) AB19(3.5,-5) AB20(4,-5) AB21(4.5,-5) AB22(5,-5) AB23(5.5,-5) AC1(-5.5,-5.5) AC2(-5,-5.5) AC3(-4.5,-5.5) AC4(-4,-5.5) AC5(-3.5,-5.5) AC7(-2.5,-5.5) AC8(-2,-5.5) AC10(-1,-5.5) AC11(-0.5,-5.5) AC13(0.5,-5.5) AC14(1,-5.5) AC16(2,-5.5) AC17(2.5,-5.5) AC19(3.5,-5.5) AC20(4,-5.5) AC21(4.5,-5.5) AC22(5,-5.5) AC23(5.5,-5.5) B1(-5.5,5) B2(-5,5) B3(-4.5,5) B4(-4,5) B5(-3.5,5) B6(-3,5) B7(-2.5,5) B8(-2,5) B9(-1.5,5) B10(-1,5) B11(-0.5,5) B12(0,5) B13(0.5,5) B14(1,5) B15(1.5,5) B16(2,5) B17(2.5,5) B18(3,5) B19(3.5,5) B20(4,5) B21(4.5,5) B22(5,5) B23(5.5,5) C1(-5.5,4.5) C2(-5,4.5) C3(-4.5,4.5) C4(-4,4.5) C5(-3.5,4.5) C6(-3,4.5) C7(-2.5,4.5) C8(-2,4.5) C9(-1.5,4.5) C10(-1,4.5) C11(-0.5,4.5) C12(0,4.5) C13(0.5,4.5) C14(1,4.5) C15(1.5,4.5) C16(2,4.5) C17(2.5,4.5) C18(3,4.5) C19(3.5,4.5) C20(4,4.5) C21(4.5,4.5) C22(5,4.5) C23(5.5,4.5) D1(-5.5,4) D2(-5,4) D3(-4.5,4) D4(-4,4) D5(-3.5,4) D6(-3,4) D7(-2.5,4) D8(-2,4) D9(-1.5,4) D10(-1,4) D11(-0.5,4) D12(0,4) D13(0.5,4) D14(1,4) D15(1.5,4) D16(2,4) D17(2.5,4) D18(3,4) D19(3.5,4) D20(4,4) D21(4.5,4) D22(5,4) D23(5.5,4) E1(-5.5,3.5) E2(-5,3.5) E3(-4.5,3.5) E4(-4,3.5) E20(4,3.5) E21(4.5,3.5) E22(5,3.5) E23(5.5,3.5) F2(-5,3) F3(-4.5,3) F4(-4,3) F20(4,3) F21(4.5,3) F22(5,3) G1(-5.5,2.5) G2(-5,2.5) G3(-4.5,2.5) G4(-4,2.5) G20(4,2.5) G21(4.5,2.5) G22(5,2.5) G23(5.5,2.5) H1(-5.5,2) H2(-5,2) H3(-4.5,2) H4(-4,2) H20(4,2) H21(4.5,2) H22(5,2) H23(5.5,2) J2(-5,1.5) J3(-4.5,1.5) J4(-4,1.5) J20(4,1.5) J21(4.5,1.5) J22(5,1.5) K1(-5.5,1) K2(-5,1) K3(-4.5,1) K4(-4,1) K20(4,1) K21(4.5,1) K22(5,1) K23(5.5,1) L1(-5.5,0.5) L2(-5,0.5) L3(-4.5,0.5) L4(-4,0.5) L20(4,0.5) L21(4.5,0.5) L22(5,0.5) L23(5.5,0.5) M2(-5,0) M3(-4.5,0) M4(-4,0) M20(4,0) M21(4.5,0) M22(5,0) N1(-5.5,-0.5) N2(-5,-0.5) N3(-4.5,-0.5) N4(-4,-0.5) N20(4,-0.5) N21(4.5,-0.5) N22(5,-0.5) N23(5.5,-0.5) P1(-5.5,-1) P2(-5,-1) P3(-4.5,-1) P4(-4,-1) P20(4,-1) P21(4.5,-1) P22(5,-1) P23(5.5,-1) R2(-5,-1.5) R3(-4.5,-1.5) R4(-4,-1.5) R20(4,-1.5) R21(4.5,-1.5) R22(5,-1.5) T1(-5.5,-2) T2(-5,-2) T3(-4.5,-2) T4(-4,-2) T20(4,-2) T21(4.5,-2) T22(5,-2) T23(5.5,-2) U1(-5.5,-2.5) U2(-5,-2.5) U3(-4.5,-2.5) U4(-4,-2.5) U20(4,-2.5) U21(4.5,-2.5) U22(5,-2.5) U23(5.5,-2.5) V2(-5,-3) V3(-4.5,-3) V4(-4,-3) V20(4,-3) V21(4.5,-3) V22(5,-3) W1(-5.5,-3.5) W2(-5,-3.5) W3(-4.5,-3.5) W4(-4,-3.5) W20(4,-3.5) W21(4.5,-3.5) W22(5,-3.5) W23(5.5,-3.5) Y1(-5.5,-4) Y2(-5,-4) Y3(-4.5,-4) Y4(-4,-4) Y5(-3.5,-4) Y6(-3,-4) Y7(-2.5,-4) Y8(-2,-4) Y9(-1.5,-4) Y10(-1,-4) Y11(-0.5,-4) Y12(0,-4) Y13(0.5,-4) Y14(1,-4) Y15(1.5,-4) Y16(2,-4) Y17(2.5,-4) Y18(3,-4) Y19(3.5,-4) Y20(4,-4) Y21(4.5,-4) Y22(5,-4) Y23(5.5,-4)
  silkscreen extent -6.25,-6.07 6.07,6.25, body extent -6.07,-6.07 6.07,6.07, height 1.21
ICC_WFQFN44-EPAD_5X6_P040 [mm]
  rect 0.8x0.2 smd mask+0.05: 1(-2.45,2.2) 2(-2.45,1.8) 3(-2.45,1.4) 4(-2.45,1) 5(-2.45,0.6) 6(-2.45,0.2) 7(-2.45,-0.2) 8(-2.45,-0.6) 9(-2.45,-1) 10(-2.45,-1.4) 11(-2.45,-1.8) 12(-2.45,-2.2) 23(2.45,-2.2) 24(2.45,-1.8) 25(2.45,-1.4) 26(2.45,-1) 27(2.45,-0.6) 28(2.45,-0.2) 29(2.45,0.2) 30(2.45,0.6) 31(2.45,1) 32(2.45,1.4) 33(2.45,1.8) 34(2.45,2.2)
  rect 0.2x0.8 smd mask+0.05: 13(-1.8,-2.95) 14(-1.4,-2.95) 15(-1,-2.95) 16(-0.6,-2.95) 17(-0.2,-2.95) 18(0.2,-2.95) 19(0.6,-2.95) 20(1,-2.95) 21(1.4,-2.95) 22(1.8,-2.95) 35(1.8,2.95) 36(1.4,2.95) 37(1,2.95) 38(0.6,2.95) 39(0.2,2.95) 40(-0.2,2.95) 41(-0.6,2.95) 42(-1,2.95) 43(-1.4,2.95) 44(-1.8,2.95)
  rect 3.6x4.6 smd paste-1.8 mask+0.05: ep(0,0)
  silkscreen extent -2.5,-3 2.5,3, body extent -2.5,-3 2.5,3, height 0.81
IND_2520_TOKO_DFE252012P [mm]
  rect 0.8x2 smd mask+0.05: 1(-1,0) 2(1,0)
  silkscreen extent -1.35,-1.12 1.35,1.12, body extent -1.35,-1.1 1.35,1.1, height 2
R0402 [mm]
  rect 0.51x0.7 smd mask+0.05: 1(-0.45,0) 2(0.45,0)
  silkscreen extent 0,-0.3 0,0.3, body extent -0.52,-0.3 0.52,0.3, height 0.4
SWI_JIUBABA_C-TS-02H-2-5-B-V-T_R_BLUE [mm] "BLUE"
  rect 0.75x1 smd mask+0.05: 1(-2.225,0.75) 2(2.225,0.75) 3(-2.225,-0.75) 4(2.225,-0.75)
  silkscreen extent -1.85,-1.6 1.85,1.6, body extent -2.45,-1.6 2.45,1.6, height 2.6

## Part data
B1: library part MCD-00172, "Switch HW SMD blue", Manufacturer=JIUBABA, Manufacturer_Part_Number="C-TS-02H-2.5-B-V-T/R BLUE"
C1 C2 C3 C4 C5 C6 C7 C8 C9 C10 C11 C12 C17 C25 C26 C61 C66 C71 C78 C80 C82: library part MCD-00006, "Capacitor, MLCC, 100nF, 16V, X7R, +/-10%, 0402, T=0.5mm", Alternate_Manufacturer=MURATA, Alternate_Manufacturer_Part_Number=GCM155R71C104KA55D, Manufacturer=YAGEO, Manufacturer_Part_Number=CC0402KRX7R7BB104, Package=C0402
C15 C16: library part MCD-01124, "Capacitor, MLCC, 10uF, 10V, X5R, +/-10%, 0603, T=0.8mm", Manufacturer=MURATA, Manufacturer_Part_Number=GRM188R61A106KAAL, Package=C0603
C18 C31 C33 C39 C42 C46: library part MCD-00099, "Capacitor, MLCC, 10uF, 10V, X5R, +/-10%, 0603, T=0,8mm", Manufacturer=MURATA, Manufacturer_Part_Number=GRM188R61A106KE69D, Package=C0603
C29 C34 C38 C40: library part MCD-00100, "Capacitor, MLCC, 22uF, 6V3, X5R, +/-20%, 0603, T=0,8mm", Manufacturer=MURATA, Manufacturer_Part_Number=GRM188R60J226MEA0J, Package=C0603
C30 C32 C35 C36 C37 C41 C45 C47 C48 C50 C53 C54 C55 C70 C75 C76 C77 C84 C92 C94 C95 C96: library part MCD-00095, "Capacitor, MLCC, 1uF, 25V, X5R, +/-10%, 0402, T=0,5mm", Alternate_Manufacturer=MURATA, Alternate_Manufacturer_Part_Number=GRM155R60J105KE19, Manufacturer_Part_Number=GRM155R61E105KA12, Package=C0402
C43 C49 C51 C52: library part MCD-00096, "Capacitor, MLCC, 4.7uF, 6V3, X5R, +/-20%, 0402, T=0,5mm", Manufacturer=MURATA, Manufacturer_Part_Number=GRM155R60J475ME87, Package=C0402
C44 C58: library part MCD-00011, "Capacitor, MLCC, 10nF, 16V, X7R, +/-10%, 0402, T=0.5mm", Manufacturer=YAGEO, Manufacturer_Part_Number=CC0402KRX7R7BB103, Package=C0402
C56 C57: library part MCD-01508, "Capacitor, MLCC, 820pF, 50V, X7R, +/-10%, 0402, T=0.55mm", Alternate_Manufacturer=N/A, Manufacturer=YAGEO, Manufacturer_Part_Number=CC0402KRX7R9BB821, Package=C0402
C67 C68 C69: library part MCD-01823, "Capacitor,MLCC, 2.2uF, 6V3, X5R,+/-10%, 0402, T=0.5mm", Manufacturer=MURATA, Manufacturer_Part_Number=GRM155R60J225KE95D, Package=C0402
C79 C81 C83: library part MCD-00012, "Capacitor, MLCC, 2.2uF, 10V, X5R, +/- 10%, 0603, T=0,8mm", Alternate_Manufacturer=KEMET, Alternate_Manufacturer_Part_Number=C0603C225K8PACTU, Manufacturer=YAGEO, Manufacturer_Part_Number=CC0603KRX5R6BB225, Package=C0603
L1 L2 L3 L4: library part MCD-01122, "Power Inductor ,1uH,4.3A max,+/-20%,0.042ohm,2520", Alternate_Manufacturer=N/A, Manufacturer=MURATA, Manufacturer_Part_Number=DFE252012P-1ROM{}P2, Package=2520
R14: library part MCD-00067, "Resistor,100R,0402,1%,1/16W", Manufacturer=YAGEO, Manufacturer_Part_Number=RC0402FR-07100RL, Package=R0402
R26 R40: library part MCD-00053, "Resistor,10K,0402,1%,1/16W", Manufacturer=YAGEO, Manufacturer_Part_Number=RC0402FR-0710KL, Package=R0402
R27 R29: library part MCD-00120, "Resistor,240R,0402,1%,1/16W", Manufacturer=YAGEO, Manufacturer_Part_Number=RC0402FR-07240RL, Package=R0402
R37 R38: library part MCD-00068, "Resistor,1K5,0402,1%,1/16W", Manufacturer=YAGEO, Manufacturer_Part_Number=RC0402FR-071K5L, Package=R0402
R41: library part MCD-00052, "Resistor,0R,0402,5%,1/16W", Manufacturer=YAGEO, Manufacturer_Part_Number=RC0402JR-070RL, Package=R0402
R43: library part MCD-00063, "Resistor,47K,0402,1%,1/16W", Manufacturer=YAGEO, Manufacturer_Part_Number=RC0402FR-0747KL, Package=R0402
U1: library part MCD-00677, "MPU TFBGA12x12 secure boot+crypto", Manufacturer=STMICROELECTRONICS
U2: library part MCD-02089, "Memory,LPDDR2,4GB,128Mbx32,533MHz,1066MT/s,1V8,POP-FBGA168", Alternate_Manufacturer=N/A, Manufacturer=ISSI, Package="12x12 168 balls PoP FBGA"
U4: library part MCD-00303, "STM PMIC WFQFN 5.0x6.0x0.80 44L 0.4 pitch", Manufacturer=STMICROELECTRONICS, Manufacturer_Part_Number=STPMU1APQR
U5: library part MCD-00110, "Memory,e-MMC,4GB,3V3,WFBGA,153pins", Manufacturer=TOSHIBA, Manufacturer_Part_Number=THGBMDG5D1LBAIL

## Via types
v1: diameter 0.4, hole 0.2, Top Layer to Bottom Layer, tented both sides, 270 vias
v2: diameter 0.6, hole 0.3, Top Layer to Bottom Layer, tented both sides, 99 vias
v3: diameter 0.25, hole 0.1, Top Layer to Signal Layer 1, tented top, 88 vias
v4: diameter 0.25, hole 0.1, Top Layer to Signal Layer 1, tented both sides, 5 vias

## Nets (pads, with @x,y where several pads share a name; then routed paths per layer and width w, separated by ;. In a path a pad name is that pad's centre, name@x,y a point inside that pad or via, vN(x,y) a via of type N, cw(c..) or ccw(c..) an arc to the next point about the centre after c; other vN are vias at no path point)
3V3: C32.2 C40.2 C78.2 C79.2 L4.2 U4.22 U4.27 U5.E6 U5.F5 U5.J10 U5.K9 | length 50.8
  Top Layer w0.1: v3(12.25,81.45) U4.27@12.25,82.025
  Top Layer w0.175: U5.J10@27.7,88.475 U5.K9@28.2,88.975 v1(28.2,89.45) ; U5.E6@29.7,86.475 U5.F5@30.2,86.975 v1(30.625,86.975)
  Top Layer w0.2: 9.725,82.5 U4.22@9.9,82.675 9.9,82.491
  Top Layer w0.3: 9.625,82.5 9.725,82.5
  Top Layer w0.4: C32.2@7.7,80.075 7.9,80.075 8.635,80.81 8.635,81.41 9.725,82.5
  Signal Layer 1 w0.2: v2(11.575,74.9) 12.25,75.575 v3(12.25,81.45)
  Signal Layer 4 w0.3: v2(8.3,80.25) 7.225,79.175 7.225,76.825 9.15,74.9 v2(10.2,74.9) v2(10.9,74.9) v2(11.575,74.9)
  Bottom Layer w0.13: C78.2@30.025,86.9 C78.2@30.125,87 ; v1@30.6,87 v1(30.625,86.975)
  Bottom Layer w0.3: v2(11.575,74.9) 17.275,80.6 17.275,82.625 18.775,84.125 22.575,84.125 25.25,86.8 25.25,87.475 C79.2@27.35,89.575 ; C79.2@27.475,89.45 28.175,89.45 29.325,88.3 29.325,87.6 C78.2@30.025,86.9 ; C78.2@30.125,87 v1@30.6,87
5V_VIN: C18.2 C31.2 C33.2 C39.2 C41.2 C51.2 R43.2 U4.8 U4.12 U4.19 U4.24 U4.28 U4.36 U4.37 | length 20.5
  Top Layer w0.2: 8.775,83.875 U4.19@9.9,83.875 ; 11.05,81.3 U4.24@11.05,82.025 ; U4.8@12.25,86.925 12.25,88.76 ; U4.28@12.65,82.025 12.65,80.975 13.625,80 C31.2@13.625,79.25 ; U4.36@15.8,83.075 16.45,83.075 C51.2@16.7,82.825 ; U4.37@15.8,83.475 16.825,83.475
  Top Layer w0.3: C41.2@7.7,83.325 8.25,83.875 8.775,83.875 ; v1(8.075,78.775) v1(8.55,78.775) v1(9,78.775) ; v2(18.575,81.45) 19.325,81.45 R43.2@19.461,81.586
  Top Layer w0.4: v2(4.725,83.15) v2(5.35,83.15) 5.735,82.765 7.335,82.765 7.7,83.13 C41.2@7.7,83.325
  Top Layer w0.45: 16.625,83.55 18.078,83.55 18.503,83.125 v2(18.575,83.125) ; C51.2@16.7,82.825 16.7,82.127 17.377,81.45 v2(18.575,81.45)
  other v1: 13.225,78.725 13.725,78.725 14.2,78.725
  other v2: 6.075,88.575 6.075,89.2 6.075,89.825 11.85,89.9 12.55,89.9
DDR_A0: U1.L20 U2.AC6 | length 22.4
  Top Layer w0.12: v1(35.65,62.95) 35.75,62.95 U1.L20@36,63.2 ; U2.AC6@51.35,66.825 v1(51.35,67.275)
  Bottom Layer w0.12: v1(35.65,62.95) 37.045,64.345 37.045,65.925 37.725,66.605 39.105,66.605 41.405,68.905 41.77,68.905 42.2,68.475 42.85,68.475 43.28,68.905 44.426,68.905 44.856,68.475 45.475,68.475 45.905,68.905 50.095,68.905 50.428,68.572 50.428,67.228 50.676,66.98 51.024,66.98 51.319,67.275 v1(51.35,67.275)
DDR_A1: U1.P22 U2.AB6 | length 21.9
  Top Layer w0.1: v1(35.625,61.95) 36.75,61.95 U1.P22@37,61.7
  Top Layer w0.12: v1@50.875,65.375 51.35,65.85 U2.AB6@51.35,66.325
  Bottom Layer w0.12: v1(35.625,61.95) 35.637,61.95 38.919,65.231 38.919,65.753 39.351,66.185 40.035,66.185 41.905,68.055 48.12,68.055 49.115,67.06 49.665,67.06 50.49,66.235 50.49,65.726 50.683,65.533
  other v1: 50.85,65.375
DDR_A2: U1.J20 U2.AC7 | length 21.4
  Top Layer w0.12: v1(35.575,64.15) 35.625,64.2 U1.J20@36,64.2 ; U2.AC7@50.85,66.825 v1(50.85,67.4)
  Bottom Layer w0.12: v1(35.575,64.15) 36.625,65.2 36.625,66.375 37.275,67.025 38.925,67.025 41.225,69.325 42,69.325 42.43,68.895 42.676,68.895 43.106,69.325 44.6,69.325 45.03,68.895 45.301,68.895 45.731,69.325 50.269,69.325 50.85,68.744 v1(50.85,67.4)
DDR_A3: U1.K22 U2.AB8 | length 22
  Top Layer w0.09: U1.K22@37,63.7 37.25,63.45 37.25,63.1 37.425,62.925 37.7,62.925 37.85,63.075 v1(37.925,63.075)
  Top Layer w0.12: v1@50.105,65.37 50.46,65.726 50.46,66.024 50.35,66.134 U2.AB8@50.35,66.325
  Bottom Layer w0.12: v1@37.938,63.063 39.8,64.925 40.514,64.925 40.775,64.664 40.775,64.25 41.014,64.011 41.286,64.011 41.7,64.425 41.7,65.575 42,65.875 42.425,65.875 42.675,65.625 42.675,64.775 43.05,64.4 43.375,64.4 43.675,64.7 44.925,64.7 45.075,64.55 45.075,64.225 45.195,64.105 45.705,64.105 45.825,64.225 45.825,64.875 46.025,65.075 46.8,65.075 47,64.875 47,64.28 47.175,64.105 48.055,64.105 48.225,64.275 48.225,64.875 48.4,65.05 48.8,65.05 49.15,64.7 49.425,64.7 v1(50.1,65.375)
DDR_A4: U1.V20 U2.AB9 | length 20.5
  Top Layer w0.12: v1@35.677,59.949 35.739,59.949 U1.V20@35.988,59.7 ; U2.AB9@49.85,66.325 49.85,66.125 v1(50.1,65.875)
  Bottom Layer w0.12: v1(35.66,59.95) 35.66,61.379 40.036,65.755 40.765,65.755 42.645,67.635 45.924,67.635 47.617,65.942 47.617,65.808 47.95,65.475 49.35,65.475 49.75,65.875 v1@50.07,65.875
DDR_A5: U1.H20 U2.W1 | length 22
  Top Layer w0.12: v1(35.65,64.95) 35.75,64.95 U1.H20@36,64.7 ; U2.W1@53.85,64.825 54.1,64.575 v1(54.225,64.575)
  Signal Layer 3 w0.12: v1(35.65,64.95) 35.636,64.95 35.287,65.299 35.287,66.126 35.474,66.313 52.472,66.313 54.211,64.575 v1(54.225,64.575)
DDR_A6: U1.W20 U2.V2 | length 20.9
  Top Layer w0.12: v1@35.3,59.59 35.645,59.59 U1.W20@36,59.235 ; v1@52.012,63.788 52.55,64.325 U2.V2@53.35,64.325
  Signal Layer 3 w0.12: v1(35.285,59.605) 35.304,59.587 40.55,59.587 43.175,62.211 43.95,62.211 44.426,62.212 44.737,62.523 50.773,62.523 v1(52.025,63.775)
DDR_A7: U1.E20 U2.U1 | length 20.3
  Top Layer w0.12: v1(35.65,65.95) 35.75,65.95 U1.E20@36,66.2 ; U2.U1@53.85,63.825 v1(54.3,63.825)
  Signal Layer 3 w0.12: v1@35.713,65.887 37.738,65.887 38.4,65.225 40.325,65.225 40.888,64.662 53.438,64.662 54.275,63.825 v1(54.3,63.825)
DDR_A8: U1.Y20 U2.T2 | length 20.3
  Top Layer w0.12: v1(35.585,59.13) U1.Y20@36,58.715 ; v1(52.925,63.575) 53.1,63.575 U2.T2@53.35,63.325
  Signal Layer 3 w0.12: v1(35.585,59.13) 40.697,59.13 43.352,61.784 44.602,61.784 44.914,62.096 51.446,62.096 v1(52.925,63.575)
DDR_A9: U1.G20 U2.T1 | length 22.4
  Top Layer w0.12: v1(35.65,65.45) 35.75,65.45 U1.G20@36,65.2 ; U2.T1@53.85,63.325 v1(54.325,63.325)
  Signal Layer 3 w0.12: v1(35.65,65.45) 36.602,65.45 37.538,64.514 40.486,64.514 41.1,63.9 44.525,63.9 44.925,63.5 45.4,63.5 45.95,64.05 46.275,64.05 46.438,63.887 46.438,63.15 46.638,62.95 49.35,62.95 50.635,64.235 53.028,64.235 53.937,63.325 v1(54.325,63.325)
DDR_CKE: R26.2 U1.T20 U2.AC3 | length 22.2
  Top Layer w0.09: U1.T20@36,60.7 36.26,60.96 36.599,60.96 36.76,61.121 36.76,61.299 36.911,61.45 37.589,61.45 37.925,61.786 v1(37.925,61.8)
  Top Layer w0.12: U2.AC3@52.85,66.825 52.6,67.075 v1(52.6,67.2) 52.6,67.575 R26.2@53.6,68.575
  Bottom Layer w0.12: v1(37.925,61.8) 39.075,62.95 39.675,62.95 40.316,63.591 42.557,63.591 42.651,63.685 49.669,63.685 51.367,65.383 51.367,66.342 52.225,67.2 v1(52.6,67.2)
DDR_CLK_N: R14.2 U1.N23 U2.Y1 | length 23.4
  Top Layer w0.09: U2.Y1@53.85,65.325 53.975,65.325 v1(54.225,65.075)
  Top Layer w0.1: U1.N23@37.5,62.2 38.65,62.2 38.915,61.935 40.353,61.935 40.488,61.8 v1(40.525,61.8)
  Bottom Layer w0.1: v1(40.525,61.8) 40.645,61.92 44.825,61.92 45.535,61.21 46.49,61.21 48.255,59.445 49.62,59.445 51.005,60.83 51.005,63.3 51.855,64.15 53.356,64.15 53.7,64.494 53.7,64.914 53.861,65.075 v1(54.225,65.075) 54.225,65.325 54.05,65.5 R14.2@54.05,65.925
DDR_CLK_P: R14.1 U1.N22 U2.Y2 | length 23.6
  Top Layer w0.09: v1(52.975,65.075) 53.225,65.325 U2.Y2@53.35,65.325
  Top Layer w0.1: U1.N22@37,62.2 37.245,62.445 37.66,62.445 37.675,62.43 38.745,62.43 39.01,62.165 40.353,62.165 40.488,62.3 v1(40.525,62.3)
  Bottom Layer w0.1: v1(40.525,62.3) 40.675,62.15 44.92,62.15 45.63,61.44 46.585,61.44 48.35,59.675 49.525,59.675 50.775,60.925 50.775,63.395 51.76,64.38 53.261,64.38 53.47,64.589 53.47,64.914 53.309,65.075 v1(52.975,65.075) 52.975,65.325 53.15,65.5 R14.1@53.15,65.925
DDR_CSN: U1.M22 U2.AB3 | length 22.1
  Top Layer w0.12: U1.M22@37,62.7 39.025,62.7 v1(39.2,62.525) ; v1(51.85,65.325) U2.AB3@52.85,66.325
  Bottom Layer w0.12: v1(39.2,62.525) 39.975,62.525 40.415,62.965 45.385,62.965 45.6,62.75 45.6,62.05 45.8,61.85 46.4,61.85 46.65,62.1 46.65,62.7 46.9,62.95 47.65,62.95 47.975,62.625 47.975,61.45 48.25,61.175 49.075,61.175 49.475,61.575 49.475,62.675 51.85,65.05 v1(51.85,65.325)
DDR_DQ0: U1.E22 U2.AA23 | length 9.6
  Top Layer w0.09: U1.E22@37,66.2 37.154,66.2 37.399,65.955 37.725,65.955 37.8,66.03 38.814,66.03
  Top Layer w0.12: 38.814,66.03 40.174,67.39 41.224,67.39 41.459,67.625 43.25,67.625 43.325,67.55 43.325,67.325 43.2,67.2 42.75,67.2 42.525,66.975 42.525,66.15 U2.AA23@42.85,65.825
DDR_DQ1: U1.F22 U2.Y22 | length 10.2
  Top Layer w0.09: U1.F22@37,65.7 37.115,65.7 37.2,65.615 38.065,65.615 38.085,65.635 39.31,65.635 v1(39.5,65.825)
  Top Layer w0.12: U2.Y22@43.35,65.325 43.525,65.15 v1(43.8,65.15)
  Signal Layer 2 w0.12: v1(39.5,65.825) 38.9,65.225 38.9,65.05 39.05,64.9 39.286,64.9 40.752,66.365 42.573,66.365 43.739,65.2 v1@43.8,65.2
DDR_DQ2: U1.H21 U2.W22 | length 10.8
  Top Layer w0.09: U1.H21@36.5,64.7 36.654,64.7 36.909,64.445 37.168,64.445 37.328,64.285 37.672,64.285 37.692,64.305 39.045,64.305 39.2,64.15 v1(39.625,64.15)
  Top Layer w0.12: U2.W22@43.35,64.825 43.35,64.79 43.949,64.79 44.3,65.141 v1(44.3,65.15)
  Signal Layer 2 w0.12: v1@39.621,64.15 39.621,64.631 40.929,65.938 42.397,65.938 43.549,64.786 43.951,64.786 44.3,65.136 v1(44.3,65.15)
DDR_DQ3: U1.E21 U2.W23 | length 9.6
  Top Layer w0.09: U1.E21@36.5,66.2 36.75,65.95 ; 36.751,65.95 37.163,65.95 37.328,65.785 37.89,65.785 37.93,65.825 38.991,65.825 39.008,65.842
  Top Layer w0.12: 39.008,65.842 40.136,66.97 40.424,66.97 40.719,66.675 40.85,66.675 41.1,66.925 41.47,66.925 41.675,67.13 42,67.13 42.105,67.025 42.105,65.976 42.4,65.681 42.4,65.403 42.2,65.203 42.2,64.925 42.3,64.825 U2.W23@42.85,64.825
DDR_DQ4: U1.J21 U2.V23 | length 10.7
  Top Layer w0.09: U1.J21@36.5,64.2 36.755,63.945 37.82,63.945 37.89,63.875 38.15,63.875
  Top Layer w0.12: 38.15,63.875 38.625,63.4 v1(38.85,63.4) ; v1(42.4,64.275) 42.45,64.325 U2.V23@42.85,64.325
  Signal Layer 2 w0.12: v1(38.85,63.4) 38.812,63.438 38.087,63.438 37.85,63.675 37.85,64.275 38.125,64.55 38.617,64.55 39.444,63.723 39.902,63.723 40.048,63.869 40.048,64.223 40.325,64.5 40.85,64.5 41.175,64.175 41.55,64.175 41.875,64.5 42.218,64.5 v1@42.4,64.318
DDR_DQ5: U1.J22 U2.U22 | length 11.5
  Top Layer w0.09: U1.J22@37,64.19 37.183,64.19 37.258,64.115 38.1,64.115
  Top Layer w0.12: 38.1,64.1 38.675,64.1 v1(39.45,63.325) ; U2.U22@43.35,63.825 43.809,63.825 44.3,63.334 v1(44.3,63.325)
  Signal Layer 2 w0.12: v1(39.45,63.325) 39.725,63.05 40.452,63.05 41.629,61.873 44.494,61.873 44.865,62.244 44.865,62.82 v1@44.33,63.355
DDR_DQ6: U1.H22 U2.T22 | length 10.8
  Top Layer w0.09: U1.H22@37,64.7 37.154,64.7 37.399,64.455 37.601,64.455 37.646,64.5 39.95,64.5 v1(40.475,63.975)
  Top Layer w0.12: U2.T22@43.35,63.325 v1(43.8,63.325)
  Signal Layer 2 w0.12: v1(40.475,63.975) 41.275,63.175 41.275,63.037 42.138,62.175 44.475,62.175 44.638,62.338 44.638,62.726 44.426,62.938 44.172,62.938 43.8,63.311 v1(43.8,63.325)
DDR_DQ7: U1.G21 U2.T23 | length 11.2
  Top Layer w0.09: U1.G21@36.515,65.2 36.76,65.445 39.405,65.445
  Top Layer w0.12: 39.405,65.445 39.845,65.445 39.975,65.575 39.975,66.215 40.205,66.445 40.355,66.445 40.55,66.25 40.55,65.875 40.61,65.815 40.81,65.815 40.93,65.935 41.1,65.935 41.175,66.01 41.175,66.406 41.219,66.45 41.275,66.505 41.545,66.505 41.685,66.365 41.685,65.802 41.866,65.622 41.866,65.463 41.55,65.147 41.55,64.981 41.98,64.551 41.98,64.101 42.265,63.816 42.265,63.482 42.432,63.315 U2.T23@42.85,63.315
DDR_DQ8: U1.T21 U2.C22 | length 11.6
  Top Layer w0.09: U1.T21@36.5,60.7 36.654,60.7 36.899,60.945 37.116,60.945 37.316,61.145 37.67,61.145 37.925,61.4 38.1,61.4 38.225,61.525 v1(38.6,61.525)
  Top Layer w0.12: U2.C22@43.35,56.825 43.6,57.075 v1(43.725,57.075)
  Signal Layer 2 w0.12: v1(38.6,61.525) 38.085,61.01 38.085,59.769 40.506,57.348 43.452,57.348 v1(43.725,57.075)
DDR_DQ9: U1.U21 U2.H22 | length 10.4
  Top Layer w0.09: U1.U21@36.5,60.2 36.74,59.96 38.26,59.96 38.45,60.15
  Top Layer w0.1: 38.45,60.15 v1@38.875,60.15
  Top Layer w0.12: U2.H22@43.35,59.325 43.6,59.575 v1(43.725,59.575)
  Signal Layer 2 w0.12: v1@38.938,60.15 38.938,60.123 40.736,58.325 43.371,58.325 43.548,58.148 43.812,58.148 44.088,58.424 44.088,58.726 43.725,59.089 43.725,59.275 v1(43.725,59.575)
  other v1: 38.925,60.15
DDR_DQ10: U1.T22 U2.E22 | length 10.9
  Top Layer w0.09: U1.T22@37,60.7 37.154,60.7
  Top Layer w0.1: 37.149,60.704 37.195,60.75 37.196,60.75 37.396,60.95 37.775,60.95 38,61.175 38.75,61.175 v1(39.1,61.525)
  Top Layer w0.12: U2.E22@43.35,57.825 43.75,57.825 v1(43.8,57.775)
  Signal Layer 2 w0.12: v1(39.1,61.525) 39.1,61.421 38.512,60.833 38.512,59.946 40.682,57.775 v1(43.8,57.775)
DDR_DQ11: U1.W21 U2.H23 | length 10
  Top Layer w0.09: U1.W21@36.5,59.2 36.755,59.455 37.168,59.455 37.328,59.615 38.962,59.615 39.139,59.439
  Top Layer w0.12: 39.139,59.439 39.262,59.315 40.875,59.315 40.93,59.37 40.93,60.93 41,61 41.325,61 41.38,60.945 41.38,60.176 41.675,59.881 41.675,59.75 41.5,59.575 41.5,59.375 41.56,59.315 42.85,59.315 U2.H23@42.85,59.325
DDR_DQ12: U1.W23 U2.E23 | length 9.5
  Top Layer w0.1: U1.W23@37.5,59.2 38.635,59.2 39.26,58.575 40.432,58.575 40.558,58.45
  Top Layer w0.12: 40.558,58.45 40.928,58.08 41.32,58.08 41.405,57.995 41.405,55.975 41.55,55.83 41.675,55.83 41.83,55.985 41.83,56.955 41.919,57.044 42.258,57.044 42.534,57.32 42.534,57.603 42.756,57.825 U2.E23@42.85,57.825
DDR_DQ13: U1.T23 U2.F22 | length 9.1
  Top Layer w0.12: U1.T23@37.5,60.7 37.875,60.7 38.14,60.965 39.165,60.965 39.325,61.125 v1(39.675,61.125) ; U2.F22@43.35,58.325 43.6,58.575 v1(43.725,58.575)
  Signal Layer 2 w0.12: v1(39.675,61.125) 39.375,60.825 39.375,60.29 40.765,58.9 41.975,58.9 42.25,59.175 43.125,59.175 v1(43.725,58.575)
DDR_DQ14: U1.W22 U2.G23 | length 9.5
  Top Layer w0.09: U1.W22@37,59.2 37.154,59.2 37.399,59.445 38.8,59.445 39.35,58.895 40.706,58.895
  Top Layer w0.12: 40.706,58.895 40.93,58.895 41.025,58.8 41.025,58.576 41.101,58.5 41.32,58.5 41.6,58.78 41.75,58.78 41.825,58.705 41.825,57.375 41.936,57.264 42.167,57.264 42.24,57.337 42.24,58.715 42.35,58.825 U2.G23@42.85,58.825
DDR_DQ15: U1.Y21 U2.D23 | length 10.2
  Top Layer w0.1: U1.Y21@36.5,58.7 36.75,58.95 38.55,58.95 39.175,58.325 40.089,58.325 40.249,58.165
  Top Layer w0.12: 40.249,58.165 40.985,57.429 40.985,55.801 41.376,55.41 41.849,55.41 42.25,55.811 42.25,56.725 U2.D23@42.85,57.325
DDR_DQ16: U1.B22 U2.AB17 | length 12.4
  Top Layer w0.1: U1.B22@37.003,67.703 37.25,67.95 37.25,68.34
  Top Layer w0.12: 37.25,68.34 37.743,68.827 v1(38.05,68.825) ; v1(45.6,65.95) 45.6,66.075 U2.AB17@45.85,66.325
  Signal Layer 2 w0.12: v1(38.05,68.825) 38.075,68.85 38.075,69.2 38.175,69.3 38.525,69.3 38.625,69.2 38.625,69.096 38.839,68.882 38.953,68.768 39.366,68.768 39.741,68.394 43.844,68.394 44.6,67.638 45.176,67.638 45.6,67.214 v1(45.6,65.95)
DDR_DQ17: U1.D22 U2.AC13 | length 14.3
  Top Layer w0.1: U1.D22@37,66.7 37.25,66.95 38.227,66.95
  Top Layer w0.12: 38.227,66.97 40.322,69.065 40.523,69.065 41.625,70.167 45.602,70.167 47.85,67.919 U2.AC13@47.85,66.825
DDR_DQ18: U1.D23 U2.AC14 | length 13.3
  Top Layer w0.12: U1.D23@37.5,66.7 38.339,66.7 40.289,68.65 40.702,68.65 41.799,69.747 43.823,69.747 44.285,69.285 44.497,69.285 44.959,69.747 45.428,69.747 47.35,67.825 U2.AC14@47.35,66.825
DDR_DQ19: U1.B21 U2.AB14 | length 14
  Top Layer w0.1: U1.B21@36.5,67.7 36.75,67.95 36.75,68.499
  Top Layer w0.12: 36.75,68.499 37.761,69.51 39.765,69.51 v1(40,69.275) ; v1(47.1,65.95) 47.35,66.2 U2.AB14@47.35,66.325
  Signal Layer 2 w0.12: v1(40,69.275) 40.027,69.248 44.198,69.248 44.954,68.492 45.158,68.492 46.454,67.196 46.454,66.7 47.1,66.054 v1(47.1,65.95)
DDR_DQ20: U1.A21 U2.AB12 | length 14.5
  Top Layer w0.12: U1.A21@36.5,68.2 36.5,68.568 37.662,69.73 40.445,69.73 v1(40.5,69.675) ; v1(48.1,65.95) 48.1,66.075 U2.AB12@48.35,66.325
  Signal Layer 2 w0.12: v1(40.5,69.675) 44.375,69.675 v1(48.1,65.95)
DDR_DQ21: U1.E23 U2.AC17 | length 13.9
  Top Layer w0.09: U1.E23@37.5,66.2 37.67,66.2 37.713,66.242 ; 42.87,68.045 42.975,68.15
  Top Layer w0.12: 37.72,66.235 38.637,66.235 40.212,67.81 41.05,67.81 41.865,68.625 42.15,68.625 42.25,68.525 42.25,68.125 42.33,68.045 42.87,68.045 ; 42.975,68.15 42.975,68.8 43.082,68.907 43.475,68.907 43.575,68.807 43.575,67.894 43.734,67.735 44.785,67.735 44.925,67.875 44.925,68.525 45.1,68.7 45.287,68.7 45.85,68.137 U2.AC17@45.85,66.825
DDR_DQ22: U1.D21 U2.AC16 | length 13.4
  Top Layer w0.1: U1.D21@36.5,66.7 36.75,66.45 37.69,66.45
  Top Layer w0.12: 37.69,66.455 38.475,66.455 40.25,68.23 40.876,68.23 41.696,69.05 42.631,69.05 42.908,69.327 43.649,69.327 43.995,68.981 43.995,68.823 44.119,68.699 44.505,68.699 44.926,69.12 45.461,69.12 46.35,68.231 U2.AC16@46.35,66.825
DDR_DQ23: U1.A22 U2.AB15 | length 12.3
  Top Layer w0.12: U1.A22@37,68.2 37,68.403 37.782,69.185 39.14,69.185 v1@39.175,69.15 ; v1(46.6,65.95) 46.6,66.075 U2.AB15@46.85,66.325
  Signal Layer 2 w0.12: v1@39.2,69.195 39.205,69.2 39.539,69.2 39.918,68.821 44.021,68.821 44.777,68.065 45.16,68.065 46.027,67.198 46.027,66.523 v1(46.6,65.95)
  other v1: 39.2,69.15
DDR_DQ24: U1.Y23 U2.A17 | length 14.1
  Top Layer w0.1: U1.Y23@37.5,58.7 38.455,58.7 39.24,57.915 39.5,57.915
  Top Layer w0.12: 39.5,57.915 39.905,57.915 40,57.82 40,57.452 40.102,57.35 40.47,57.35 40.565,57.255 40.565,55.627 41.262,54.93 42.405,54.93 42.492,55.017 42.492,55.358 42.633,55.5 43.1,55.5 43.191,55.409 43.191,55.034 43.295,54.93 44.255,54.93 44.384,55.059 44.384,55.225 44.509,55.35 44.62,55.35 45.04,54.93 46.275,54.93 46.345,55 46.345,55.236 46.206,55.375 45.95,55.375 45.86,55.465 U2.A17@45.86,55.825
DDR_DQ25: U1.Y22 U2.A16 | length 13.8
  Top Layer w0.09: U1.Y22@37,58.7 37.25,58.45 38.429,58.45 40.145,56.734 40.15,56.729 40.15,56.45
  Top Layer w0.12: 40.145,56.734 40.145,55.453 41.088,54.51 46.449,54.51 46.765,54.826 46.765,55.41 U2.A16@46.35,55.825
DDR_DQ26: U1.AB21 U2.B15 | length 14.1
  Top Layer w0.09: U1.AB21@36.5,57.7 36.5,57.545 36.755,57.29 36.755,56.894
  Top Layer w0.12: 36.755,56.894 38.649,55 v1(38.7,55) ; U2.B15@46.85,56.325 v1(46.85,56.775)
  Signal Layer 2 w0.12: v1(38.7,55) 38.975,55 39.4,55.425 39.69,55.425 40.455,54.659 41.377,54.659 41.521,54.804 41.754,54.804 41.898,54.66 42.602,54.66 42.721,54.779 43.067,54.779 43.187,54.66 43.425,54.66 45.215,54.659 46.85,56.294 v1(46.85,56.775)
DDR_DQ27: U1.AB20 U2.B12 | length 15.9
  Top Layer w0.1: U1.AB20@36,57.7 36.25,57.45 36.25,56.63 36.477,56.402
  Top Layer w0.12: 36.477,56.402 39.074,53.806 39.744,53.806 v1(39.75,53.8) ; v1(48.1,56.7) 48.1,56.575 U2.B12@48.35,56.325
  Signal Layer 2 w0.12: v1@39.75,53.806 45.286,53.806 48.1,56.619 v1(48.1,56.7)
DDR_DQ28: U1.AC22 U2.B17 | length 13.1
  Top Layer w0.12: U1.AC22@37,57.2 37,56.96 38.46,55.5 v1(38.7,55.5) ; v1(45.6,56.7) 45.6,56.575 U2.B17@45.85,56.325
  Signal Layer 2 w0.12: v1(38.7,55.5) 38.785,55.5 39.137,55.852 39.867,55.852 40.632,55.086 41.2,55.086 41.375,55.261 41.375,55.437 41.563,55.625 41.775,55.625 41.975,55.425 41.975,55.187 42.075,55.087 42.425,55.087 42.55,55.212 42.55,55.425 42.662,55.537 43.125,55.537 43.236,55.425 43.236,55.213 43.363,55.087 45.251,55.087 45.6,55.436 v1(45.6,56.7)
DDR_DQ29: U1.AC21 U2.B14 | length 14.1
  Top Layer w0.12: U1.AC21@36.5,57.2 36.5,56.691 38.591,54.6 39.05,54.6 v1(39.3,54.35) ; U2.B14@47.35,56.325 v1(47.35,56.775)
  Signal Layer 2 w0.12: v1(39.3,54.35) 39.983,54.35 40.1,54.233 45.251,54.233 47.35,56.332 v1(47.35,56.775)
DDR_DQ30: U1.AA23 U2.A14 | length 13.8
  Top Layer w0.1: U1.AA23@37.5,58.2 38.215,58.2 39.725,56.69 39.733,56.683
  Top Layer w0.12: 39.725,56.69 39.725,55.279 40.914,54.09 46.623,54.09 47.43,54.897 47.43,55.3 47.35,55.38 U2.A14@47.35,55.825 U2.A14@47.375,55.8
DDR_DQ31: U1.AA22 U2.A13 | length 15.2
  Top Layer w0.1: U1.AA22@37,58.2 37.25,57.95 38.075,57.95 38.983,57.042
  Top Layer w0.12: 38.983,57.042 39.305,56.72 39.305,55.105 40.74,53.67 46.797,53.67 47.85,54.723 U2.A13@47.85,55.825
DDR_DQM0: U1.H23 U2.N23 | length 10.5
  Top Layer w0.09: U1.H23@37.5,64.7 38.56,64.7 38.6,64.74 40.36,64.74
  Top Layer w0.12: 40.36,64.74 40.427,64.673 40.625,64.475 40.775,64.475 40.915,64.615 41.322,64.615 41.56,64.377 41.56,64.11 41.475,64.025 41.05,64.025 40.9,63.875 40.9,63.675 41,63.575 41.431,63.575 41.575,63.431 41.575,63.2 41.694,63.081 41.925,63.081 42.035,62.971 42.035,62.56 41.94,62.465 41.3,62.465 41.185,62.35 41.185,62.175 41.31,62.05 42.172,62.05 42.397,61.825 U2.N23@42.85,61.825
